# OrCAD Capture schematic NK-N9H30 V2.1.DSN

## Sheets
1 System Block: size A; title: NK-N9H30; rev: 2.1; company: nuvoTon Technology Corp.; note: System Block
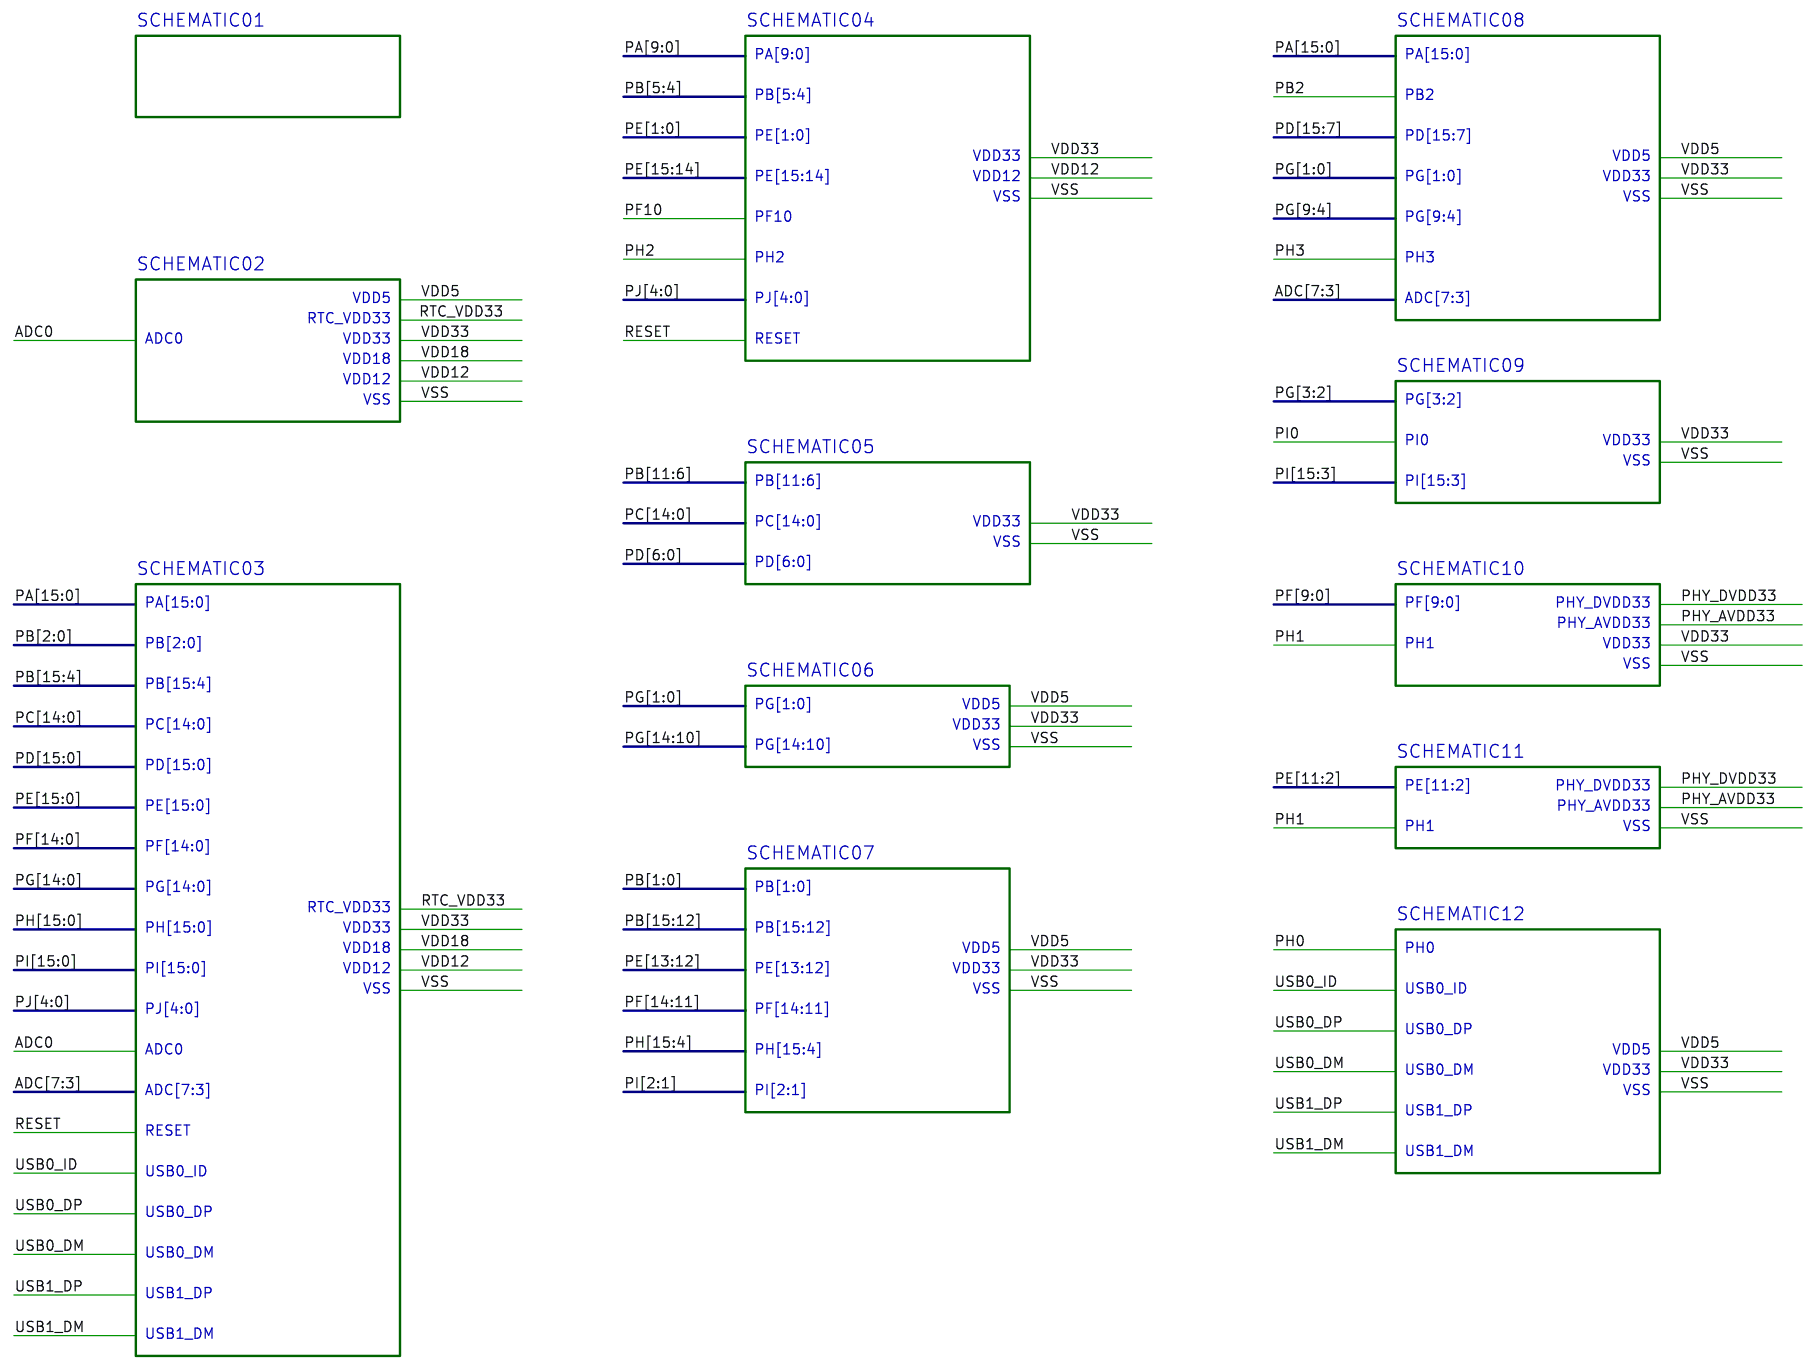
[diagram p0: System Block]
2 RMII_1_PE: size A; note: RMII_1_PE; block SCHEMATIC11
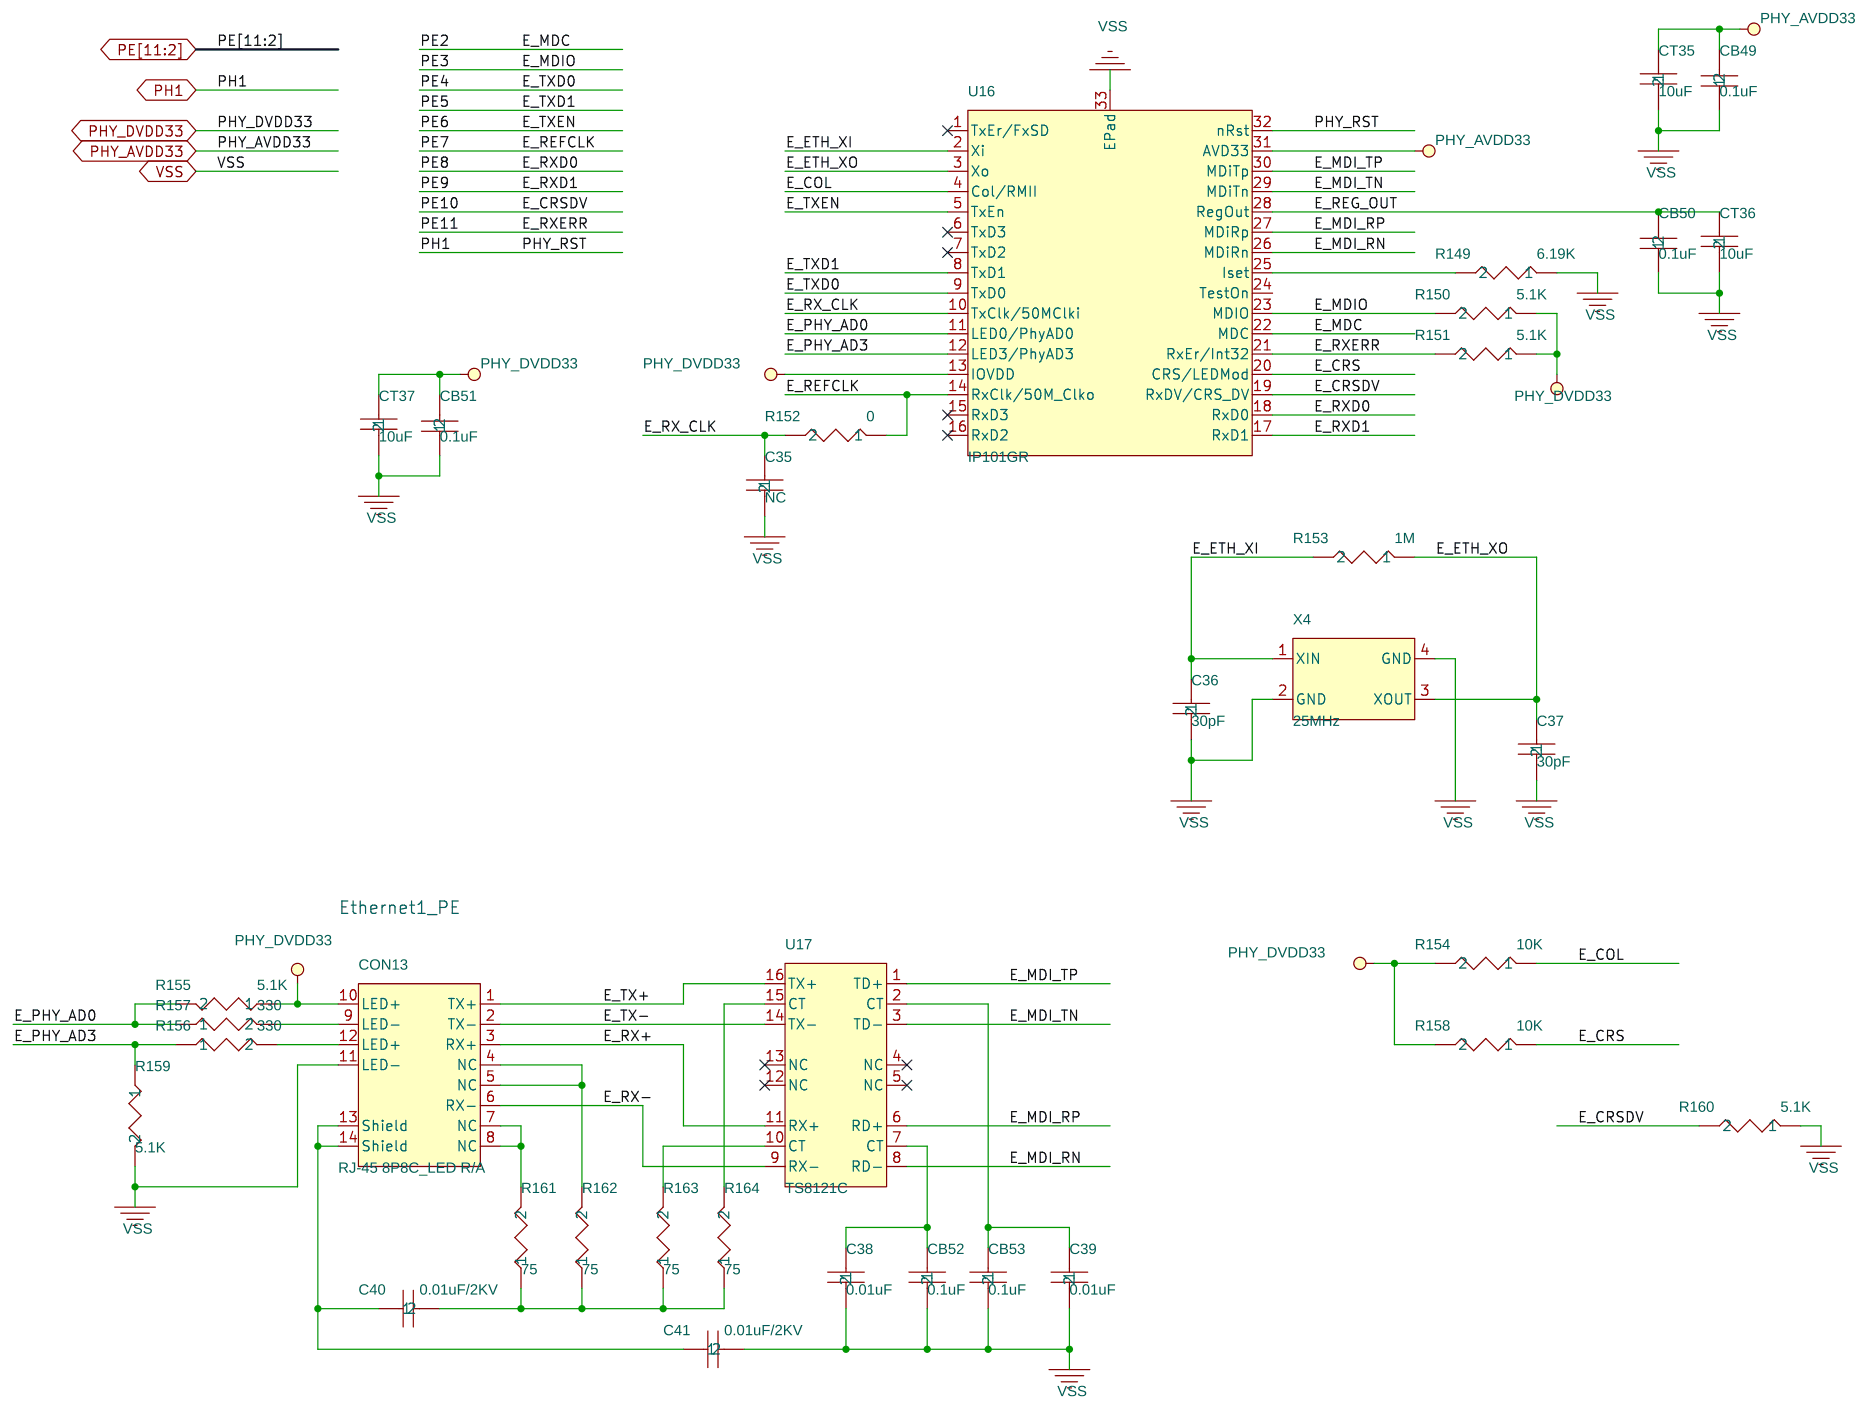
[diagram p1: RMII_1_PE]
3 RS-232_2: size A; note: RS-232_2; block SCHEMATIC07
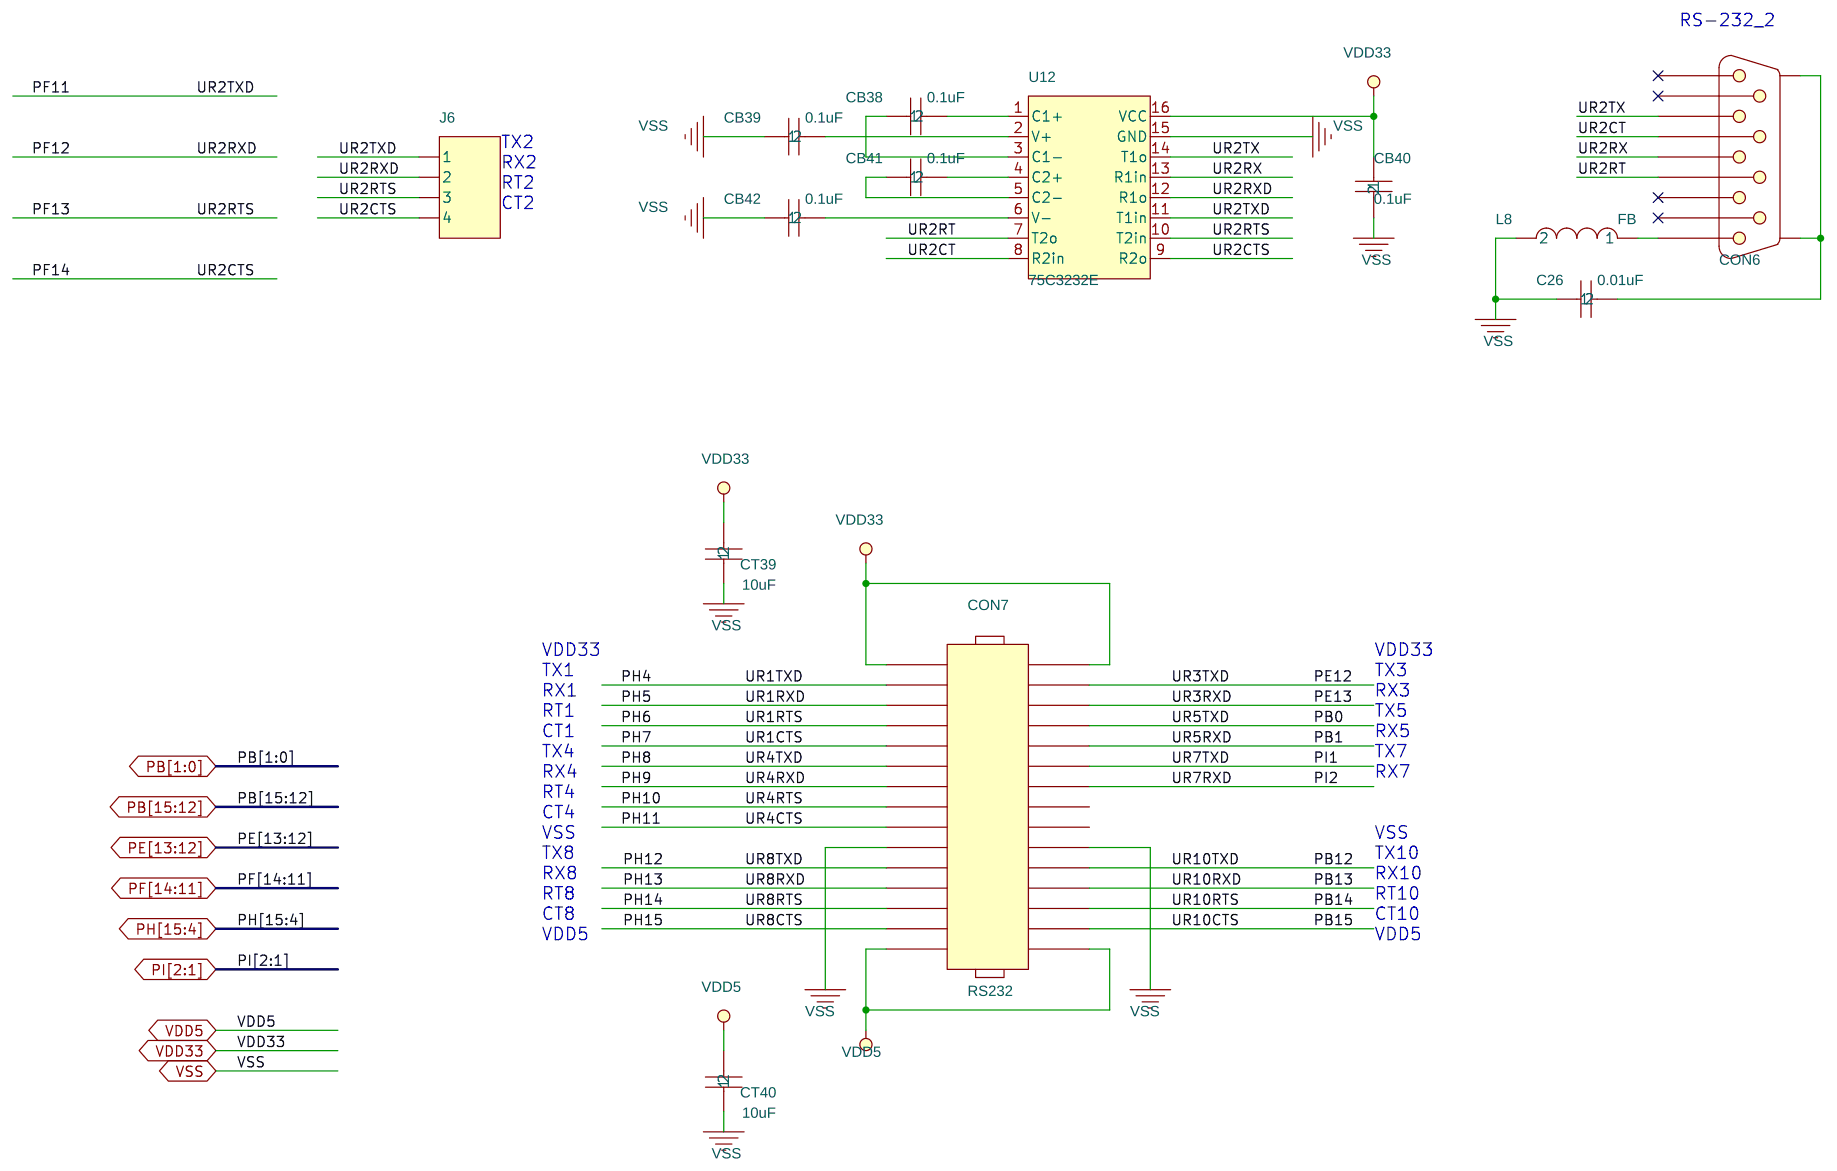
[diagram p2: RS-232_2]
4 CMOS Sensor, I2C_1, CAN_0: size A; note: CMOS Sensor, I2C_1, CAN_0; block SCHEMATIC09
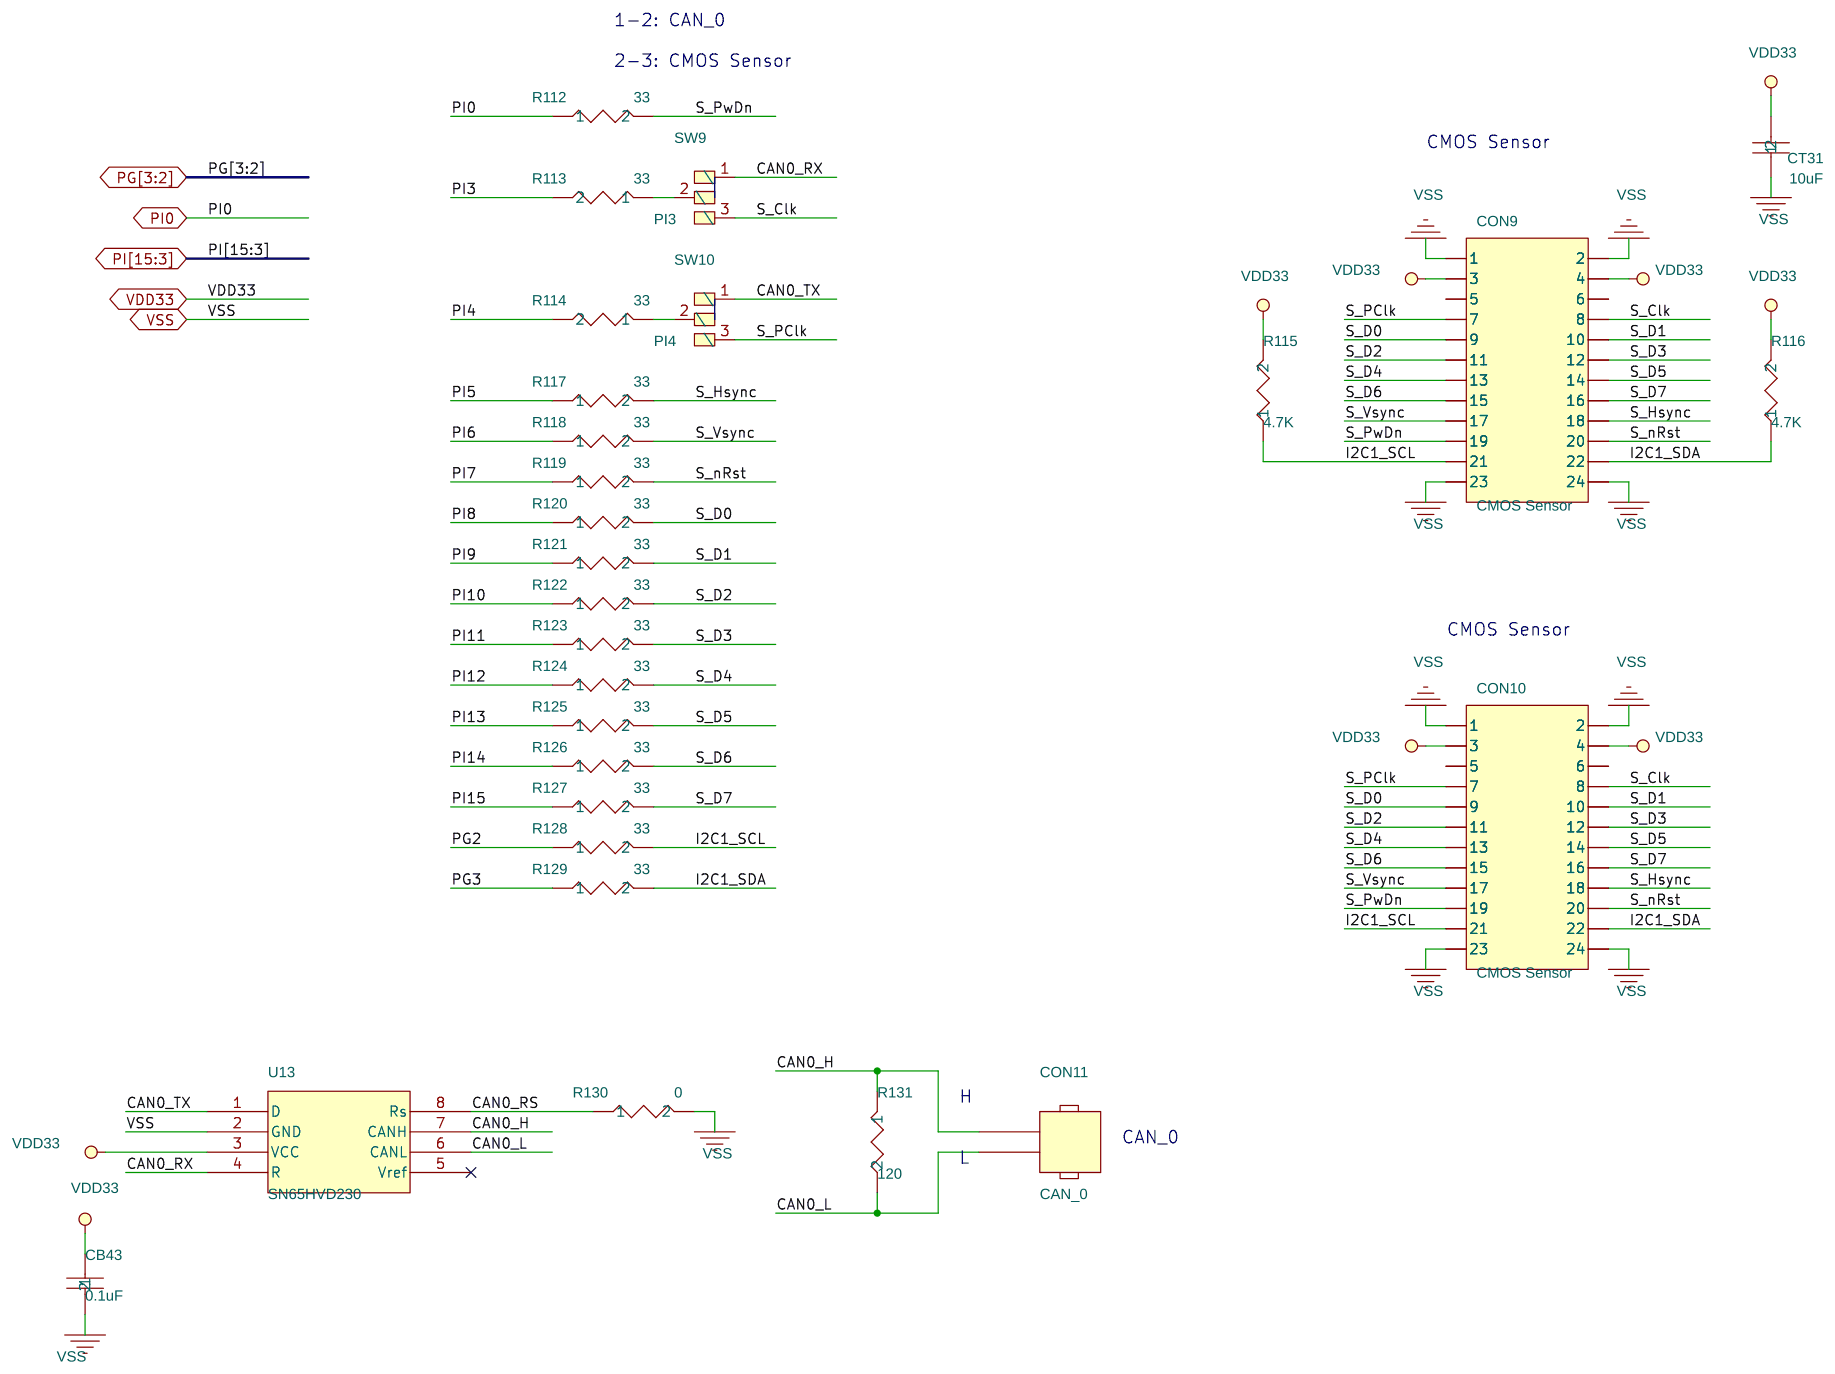
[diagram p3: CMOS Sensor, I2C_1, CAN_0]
5 I2S, I2C_0, RS-485_6: size A; note: I2S, I2C_0, RS-485_6; block SCHEMATIC06
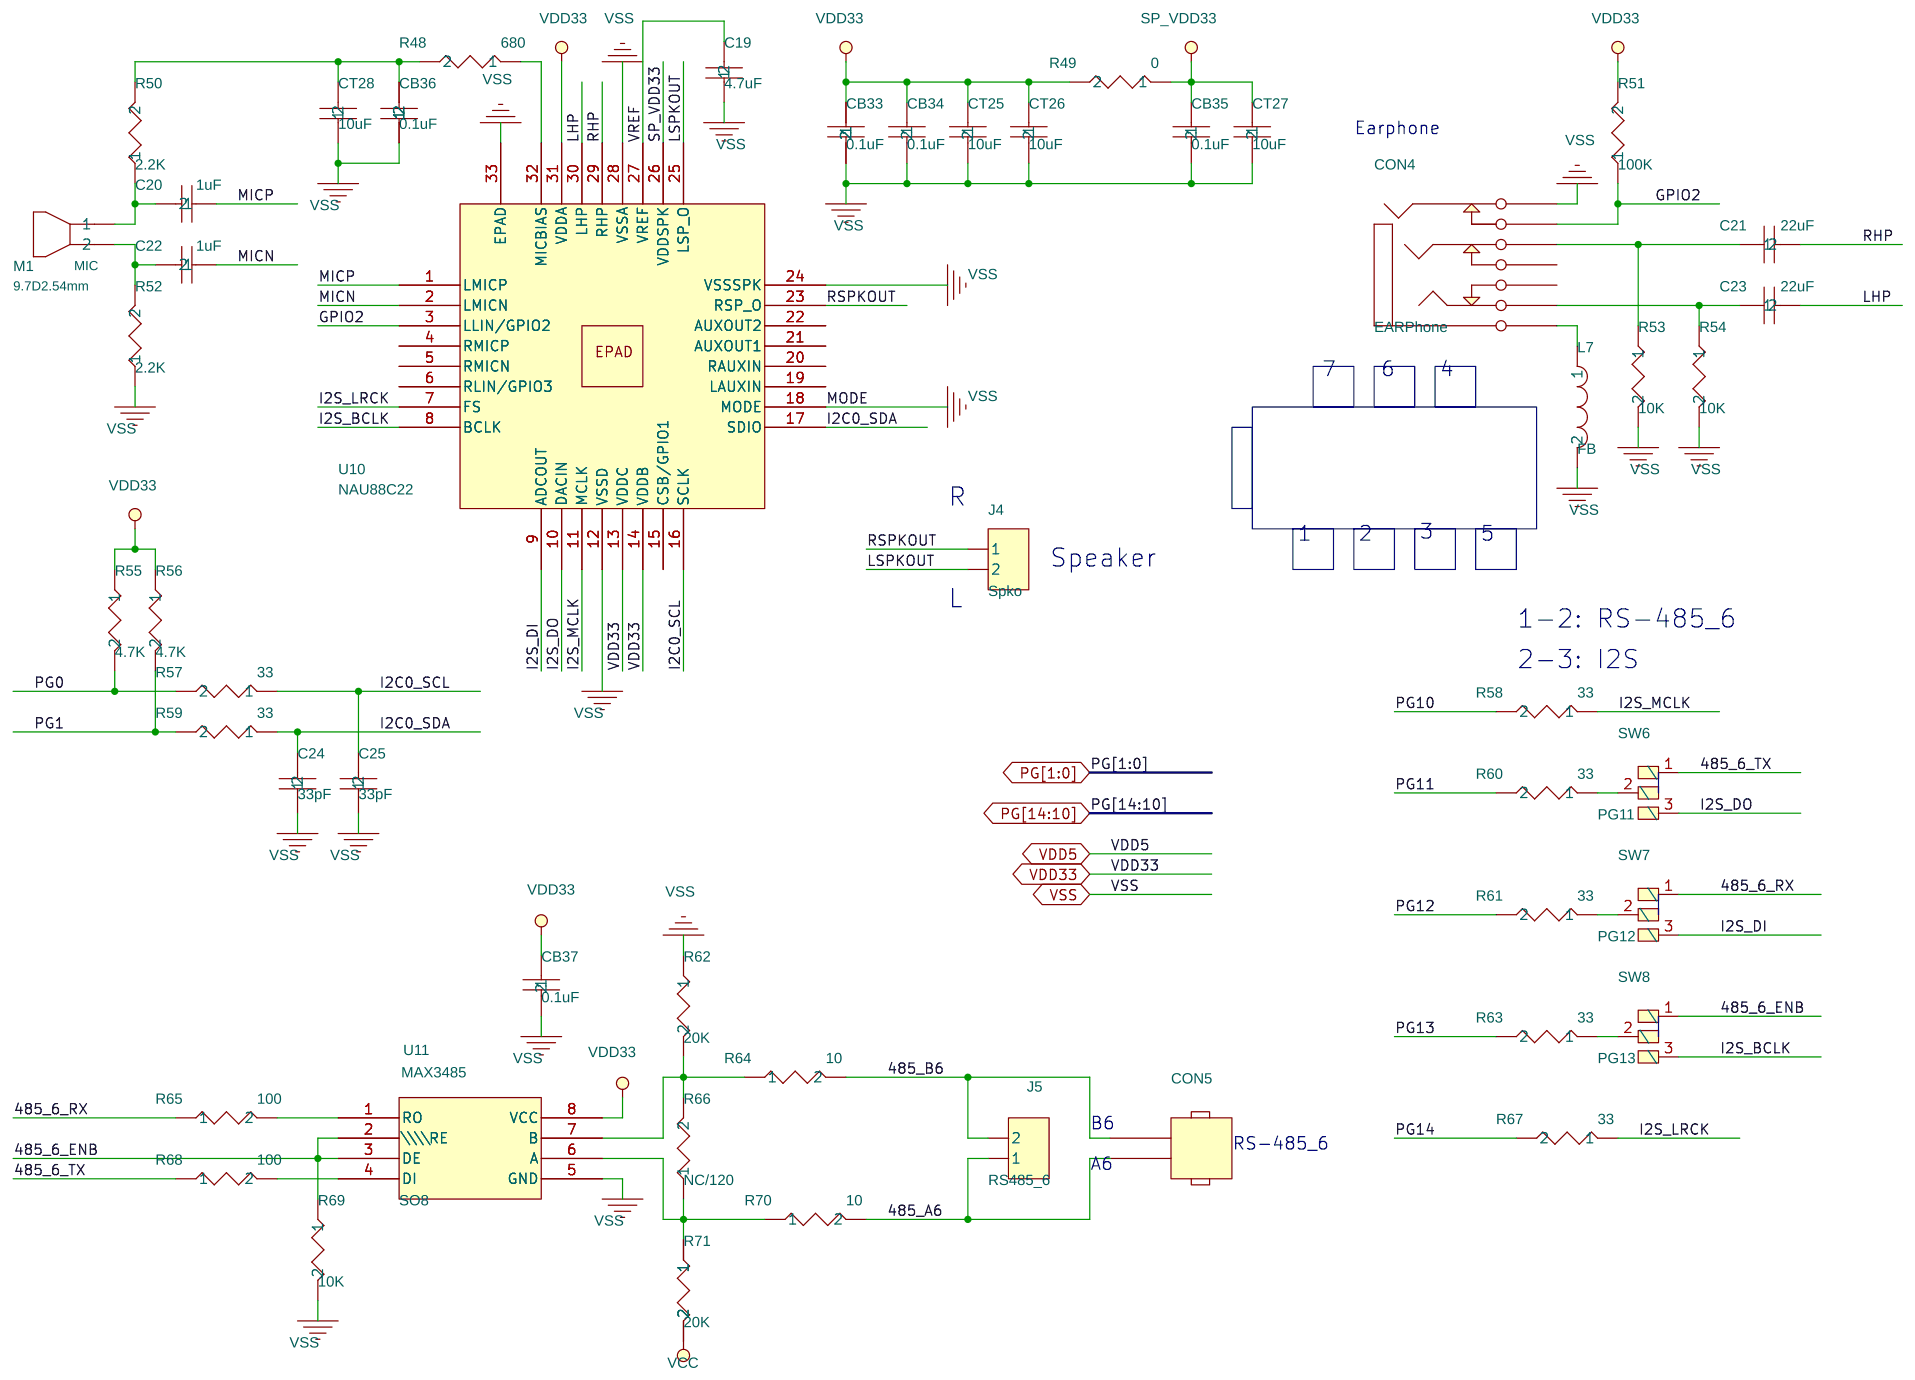
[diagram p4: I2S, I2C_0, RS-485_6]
6 LCD: size A; note: LCD; block SCHEMATIC08
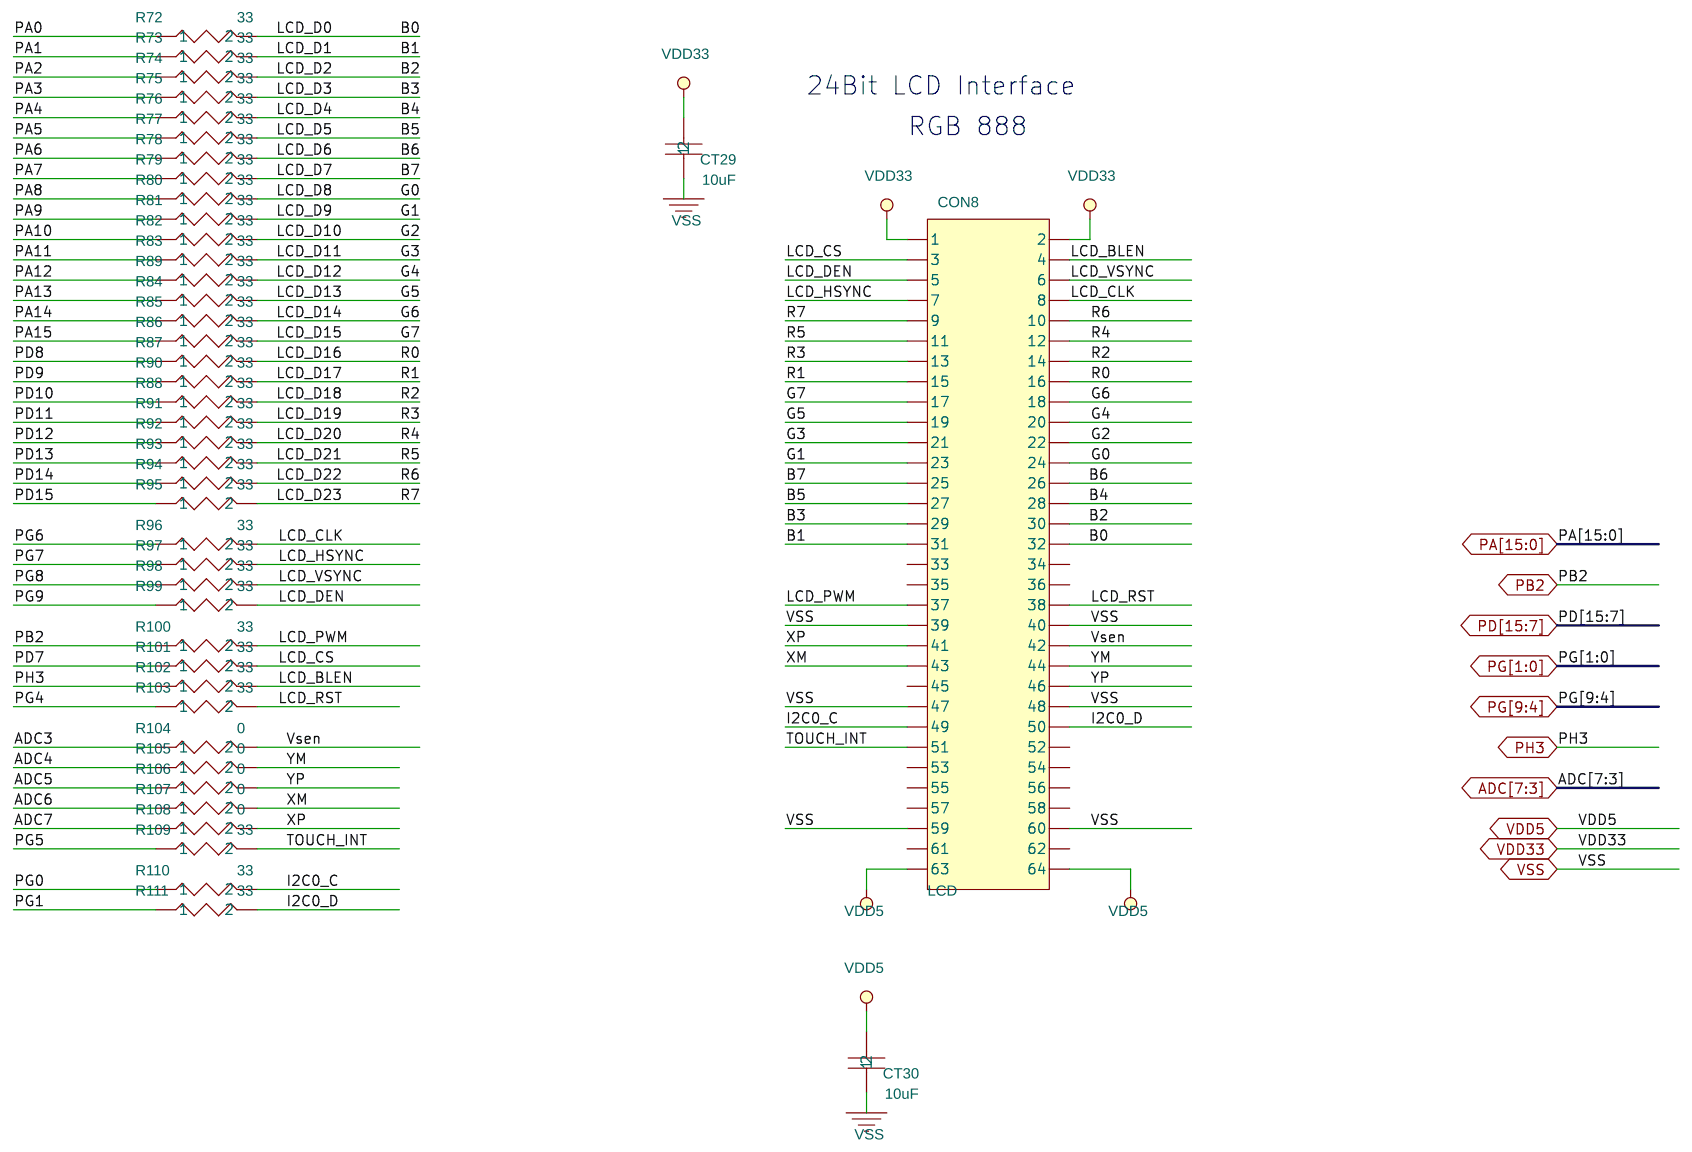
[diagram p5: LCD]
7 USB: size A; note: USB; block SCHEMATIC12
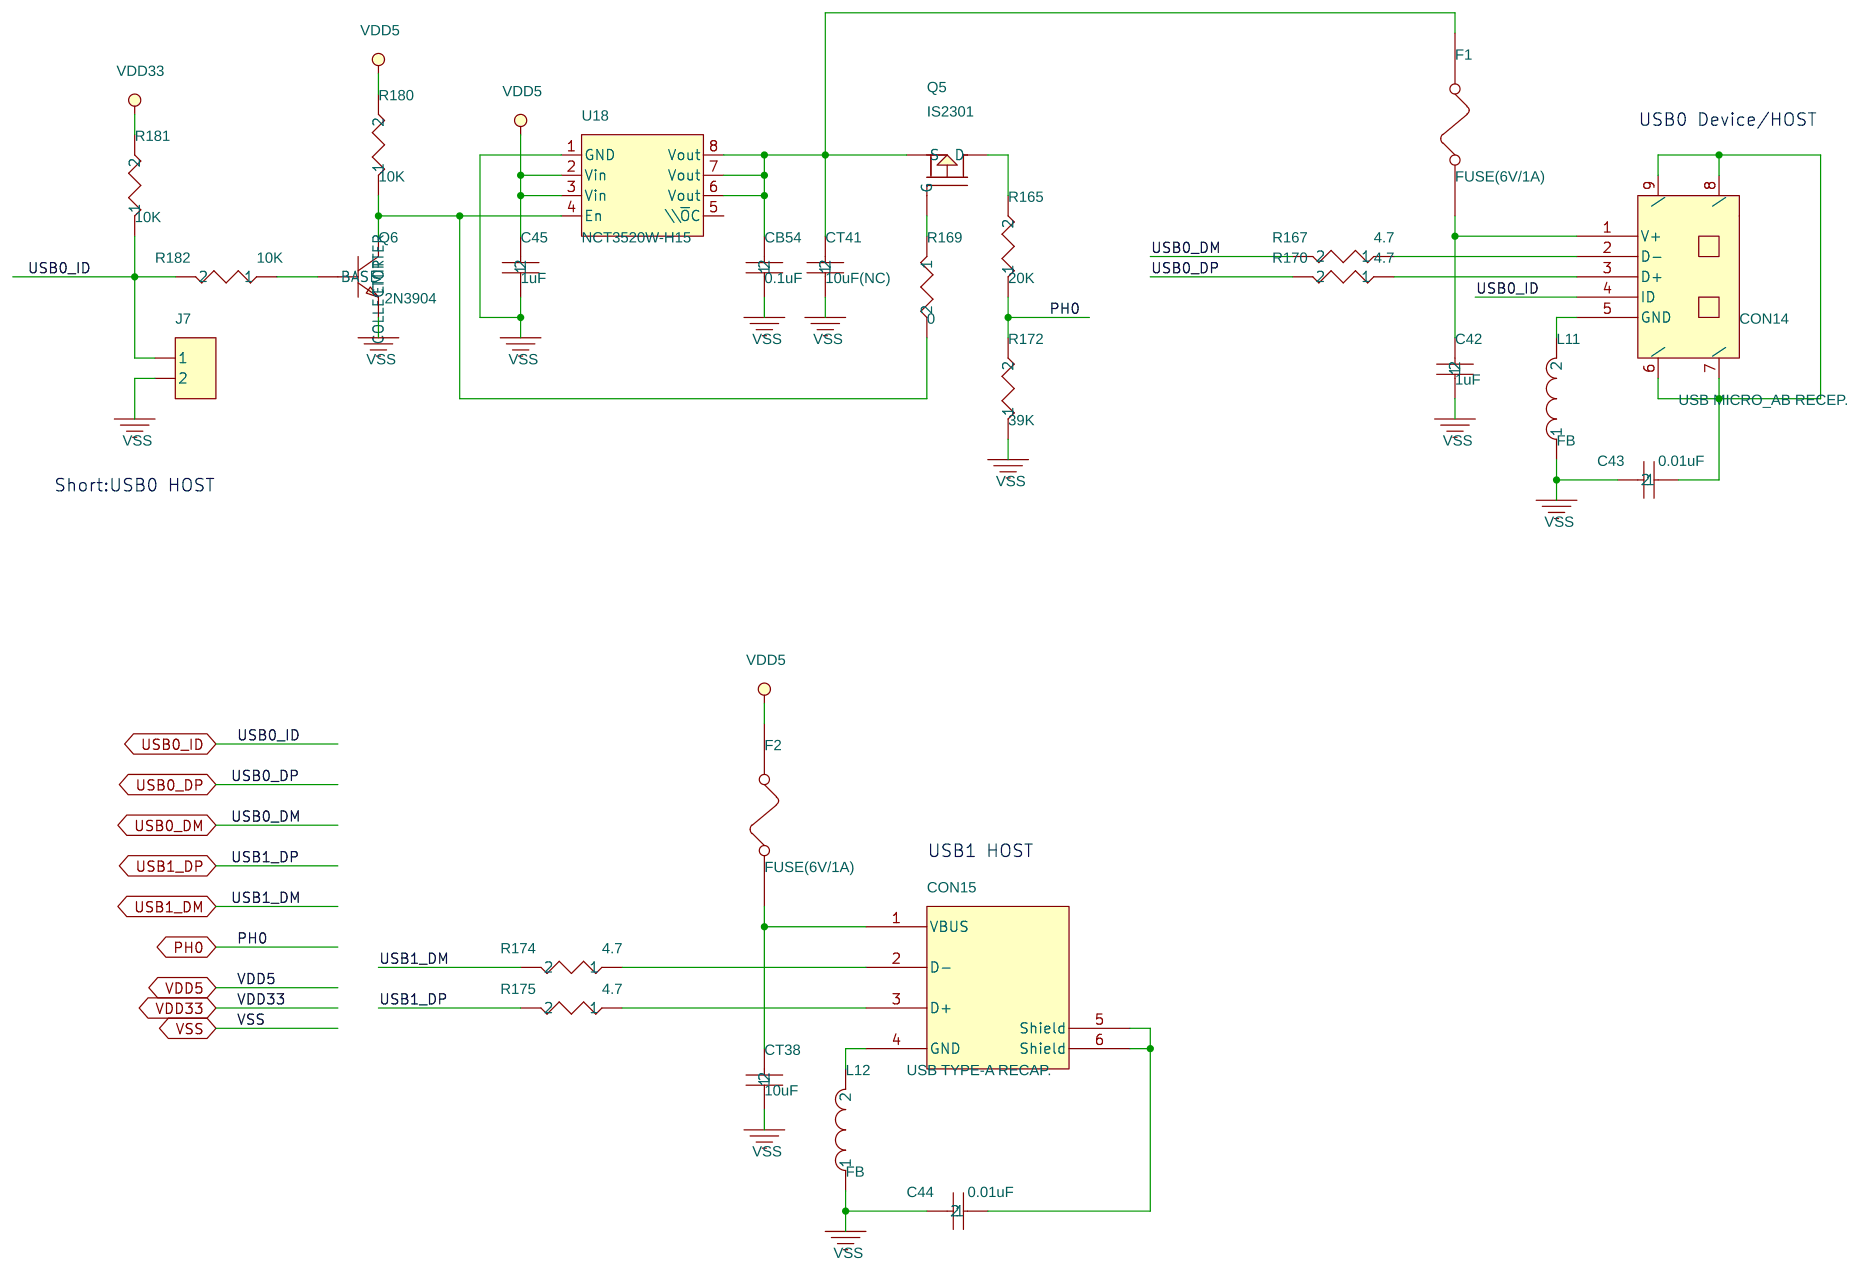
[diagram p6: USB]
8 RMII_0_PF: size A; note: RMII_0_PF; block SCHEMATIC10
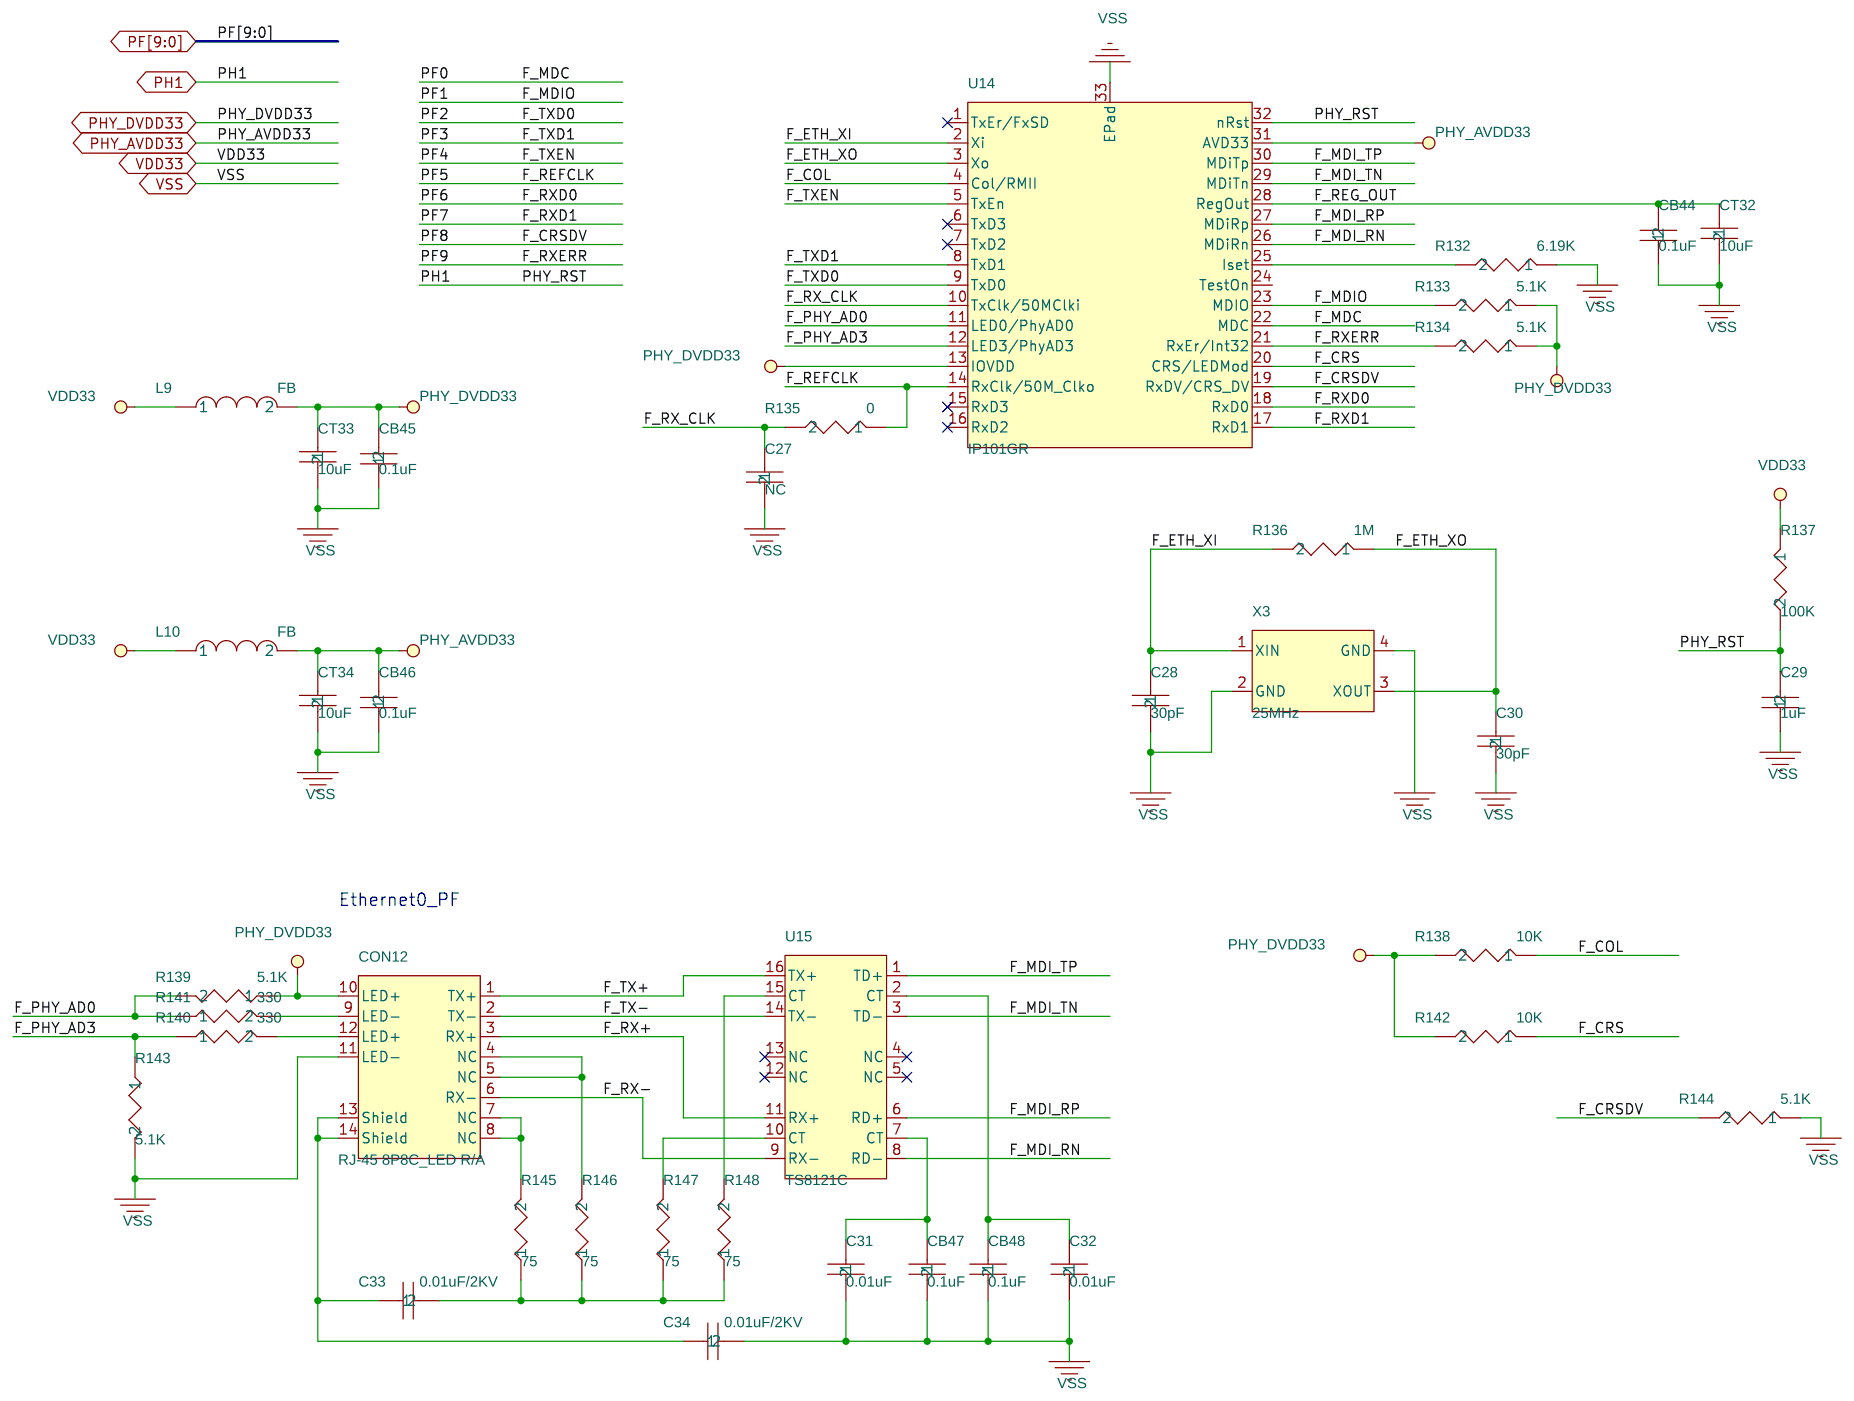
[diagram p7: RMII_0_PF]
9 Setting, ICE, RS-232_0, Key: size A; note: Setting, ICE, RS-232_0, Key; block SCHEMATIC04
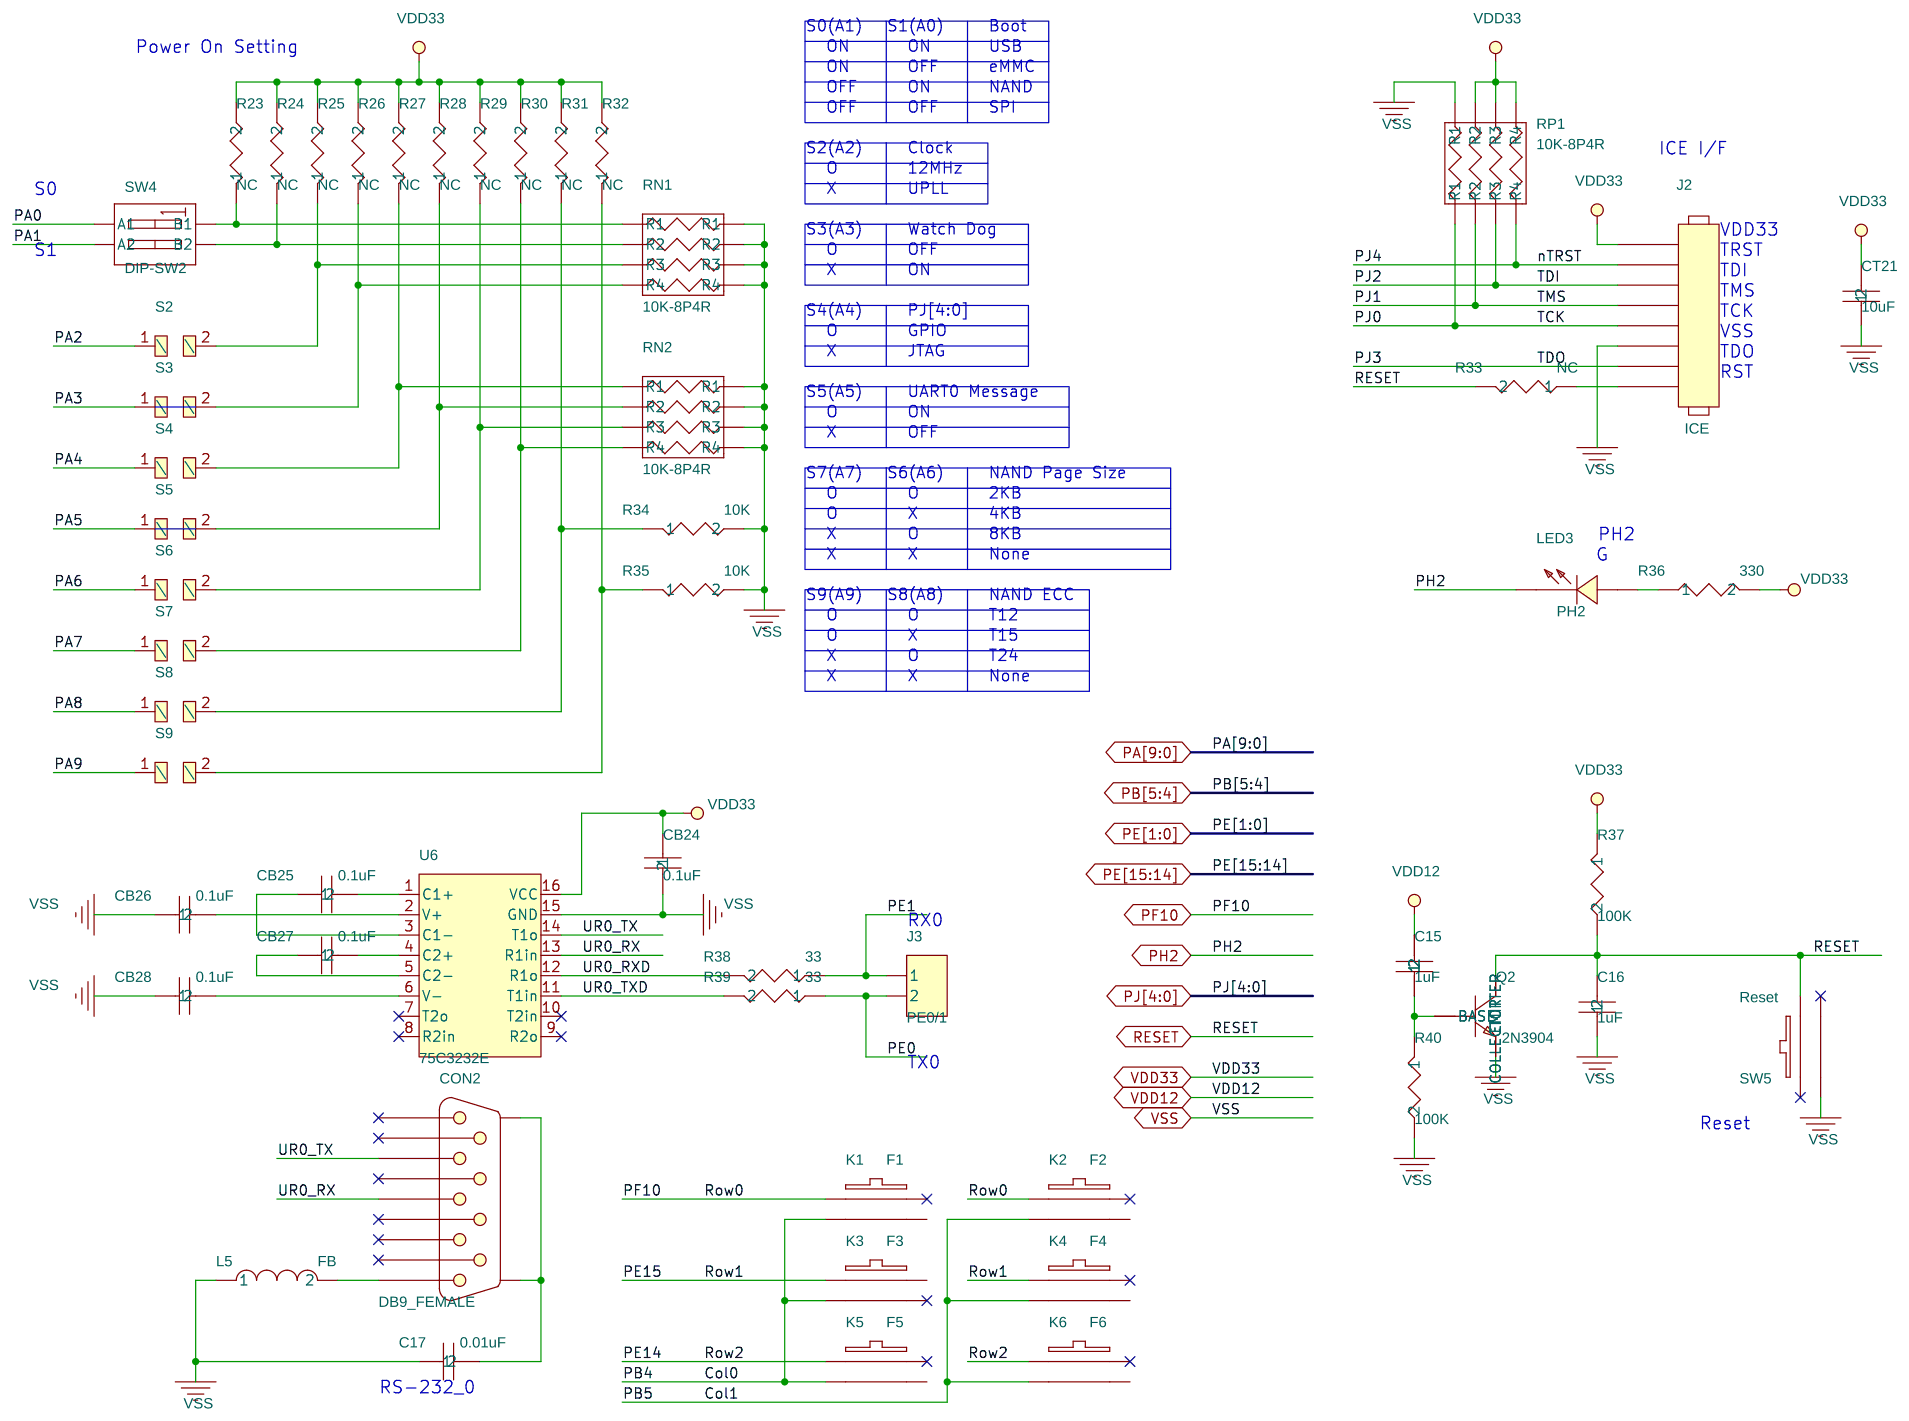
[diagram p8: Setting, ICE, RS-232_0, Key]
10 Power: size A; note: Power; block SCHEMATIC02
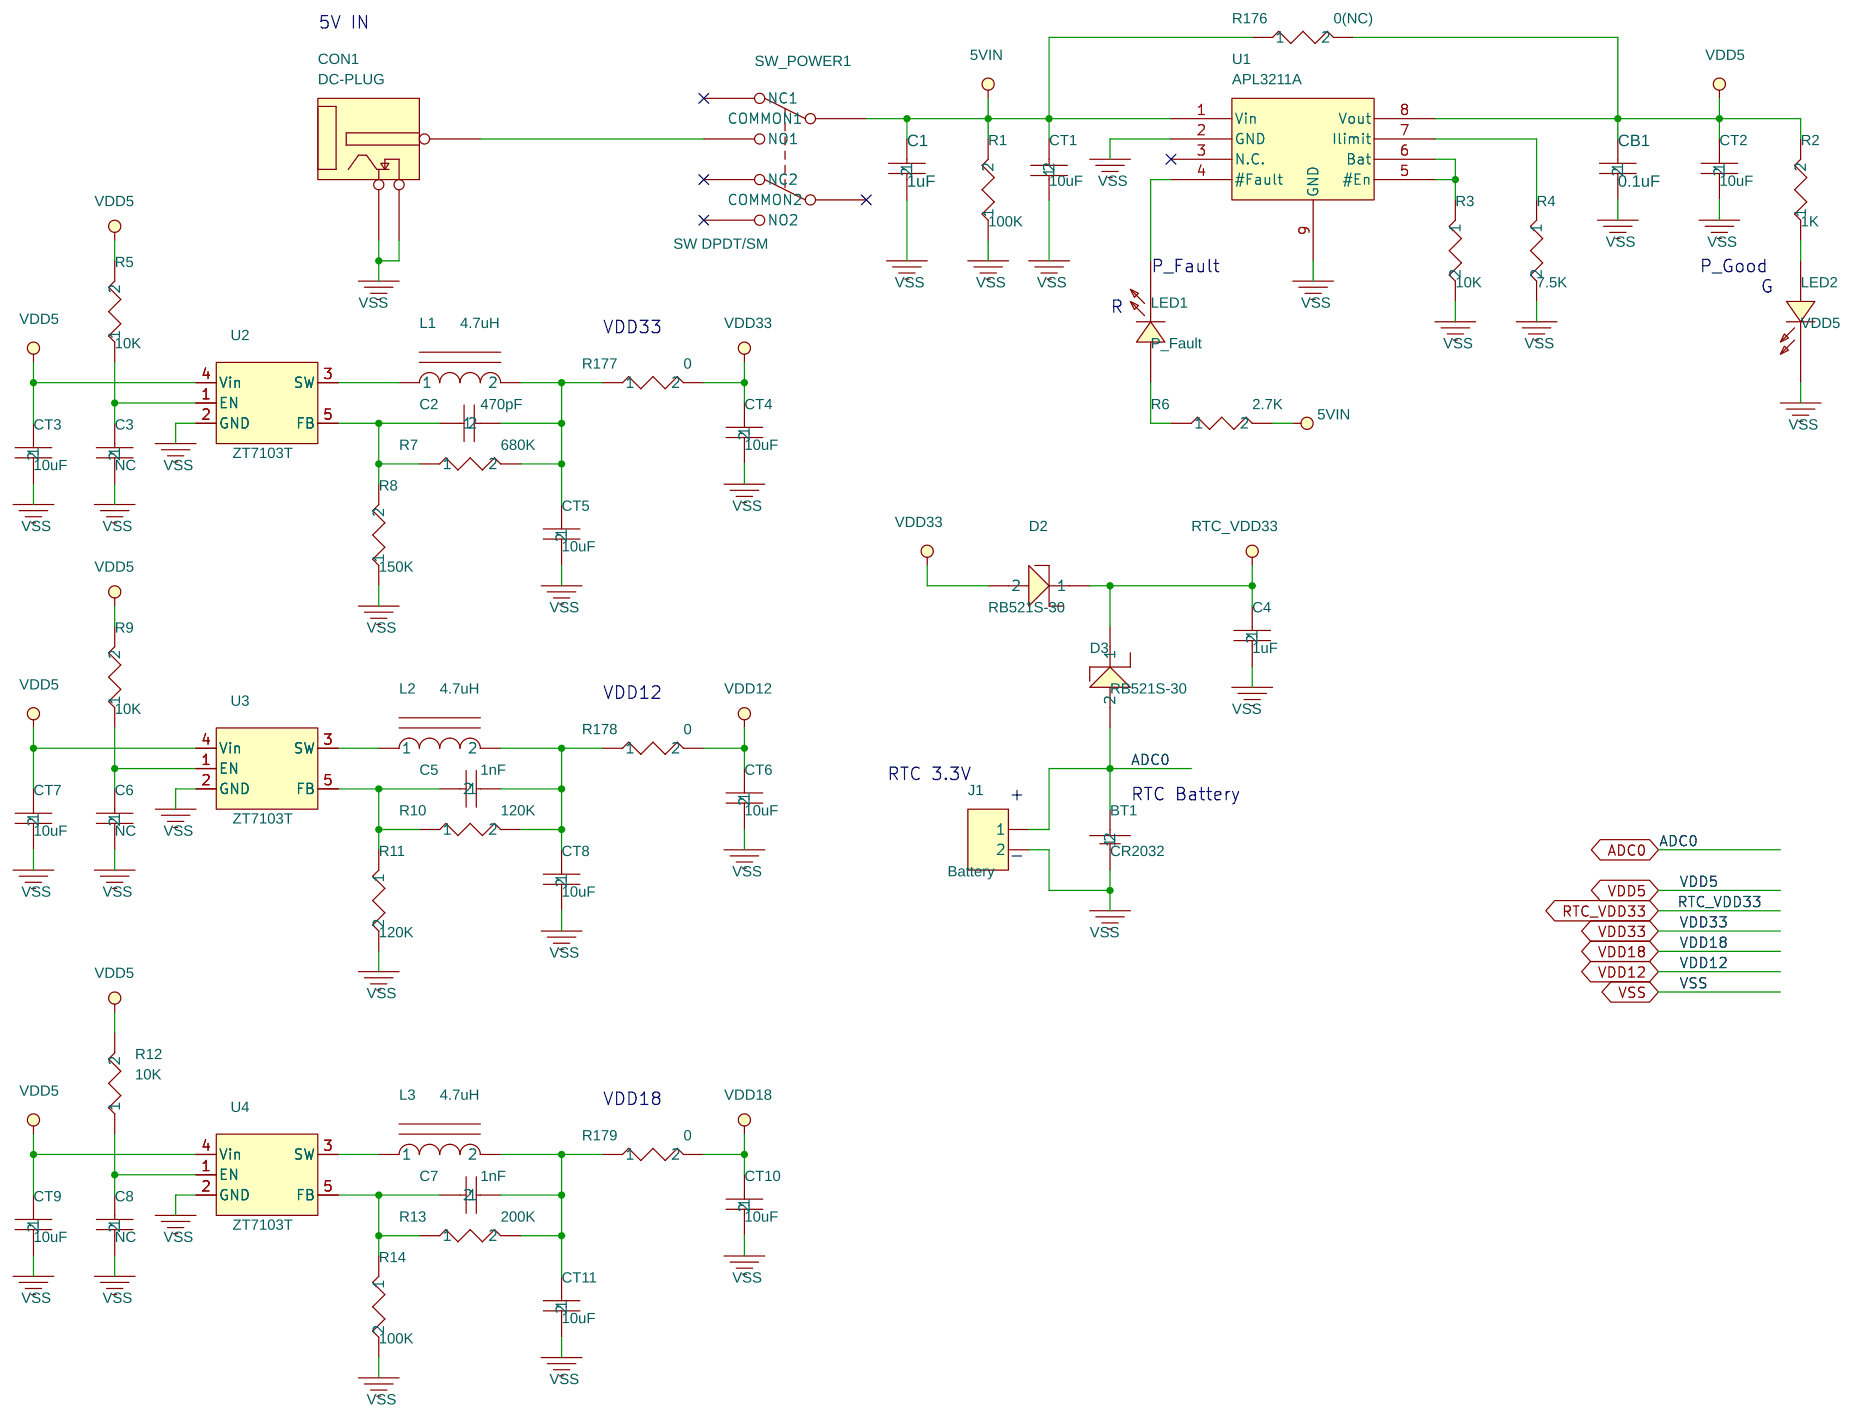
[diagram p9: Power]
11 GPIO List: note: GPIO List
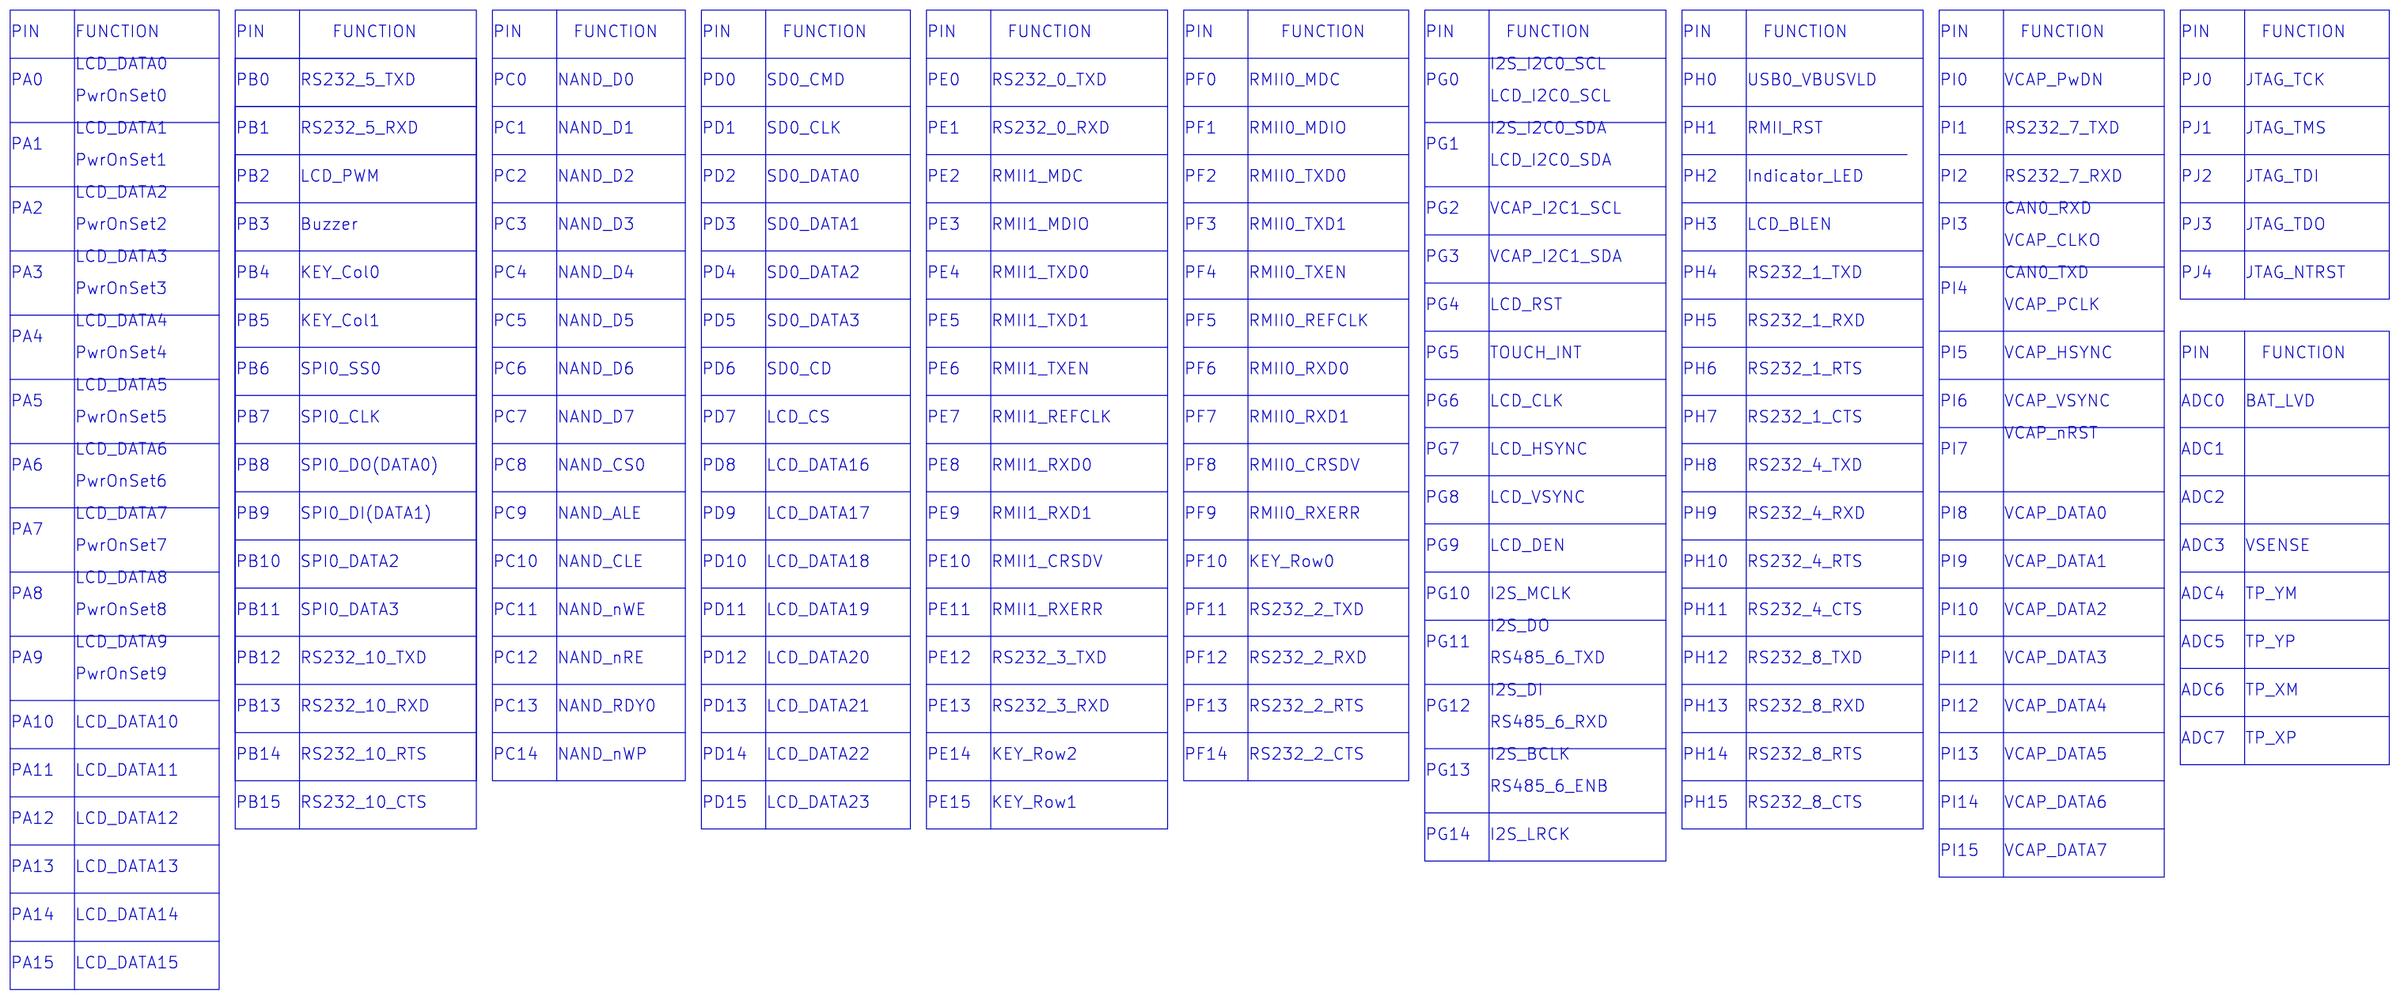
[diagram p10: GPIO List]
12 Memory: size A; note: Memory; block SCHEMATIC05
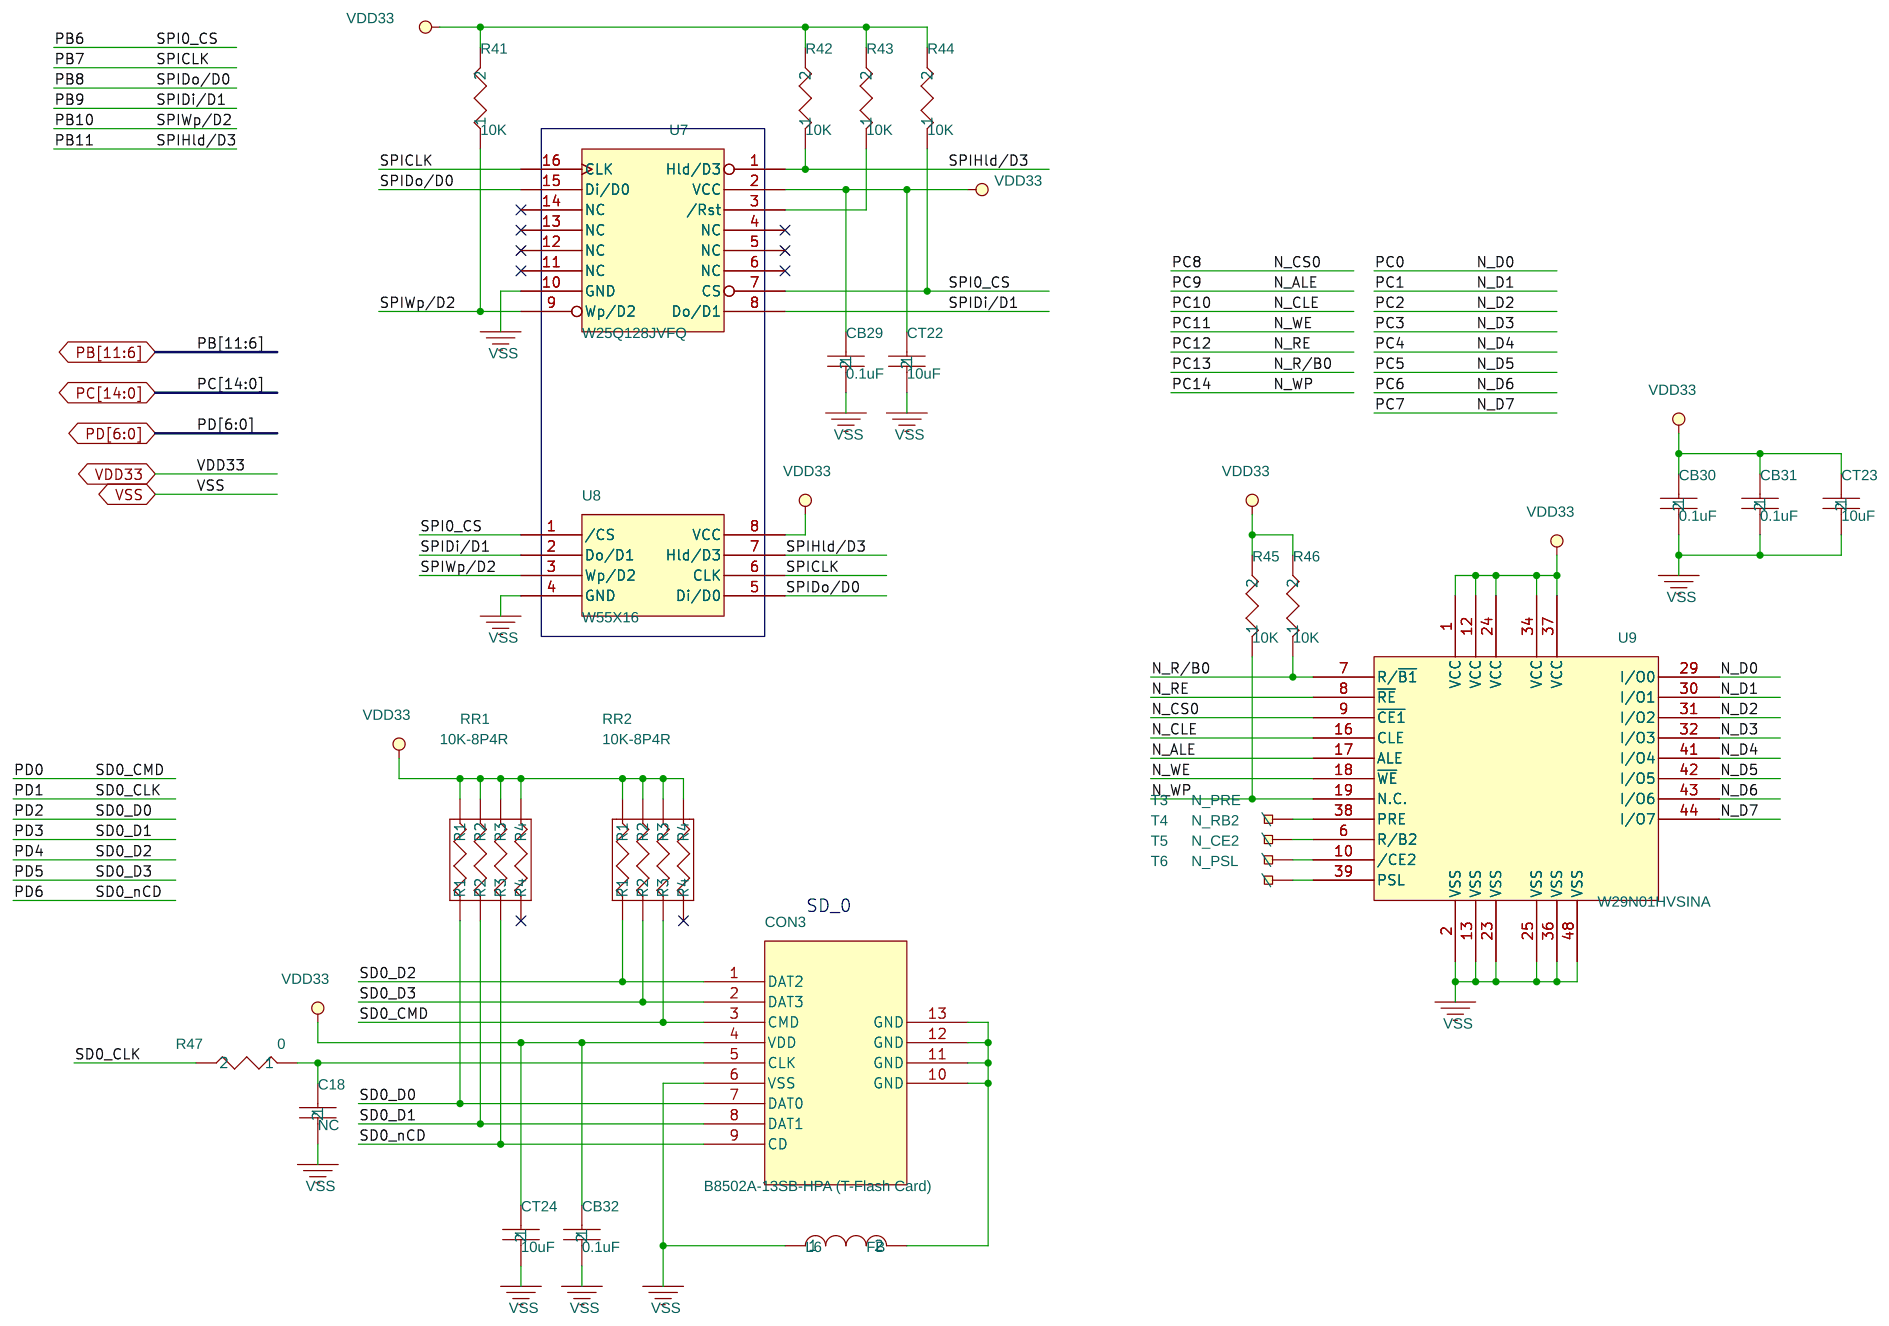
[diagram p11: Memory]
13 N9H30F61IEC: size B; note: N9H30F61IEC; block SCHEMATIC03
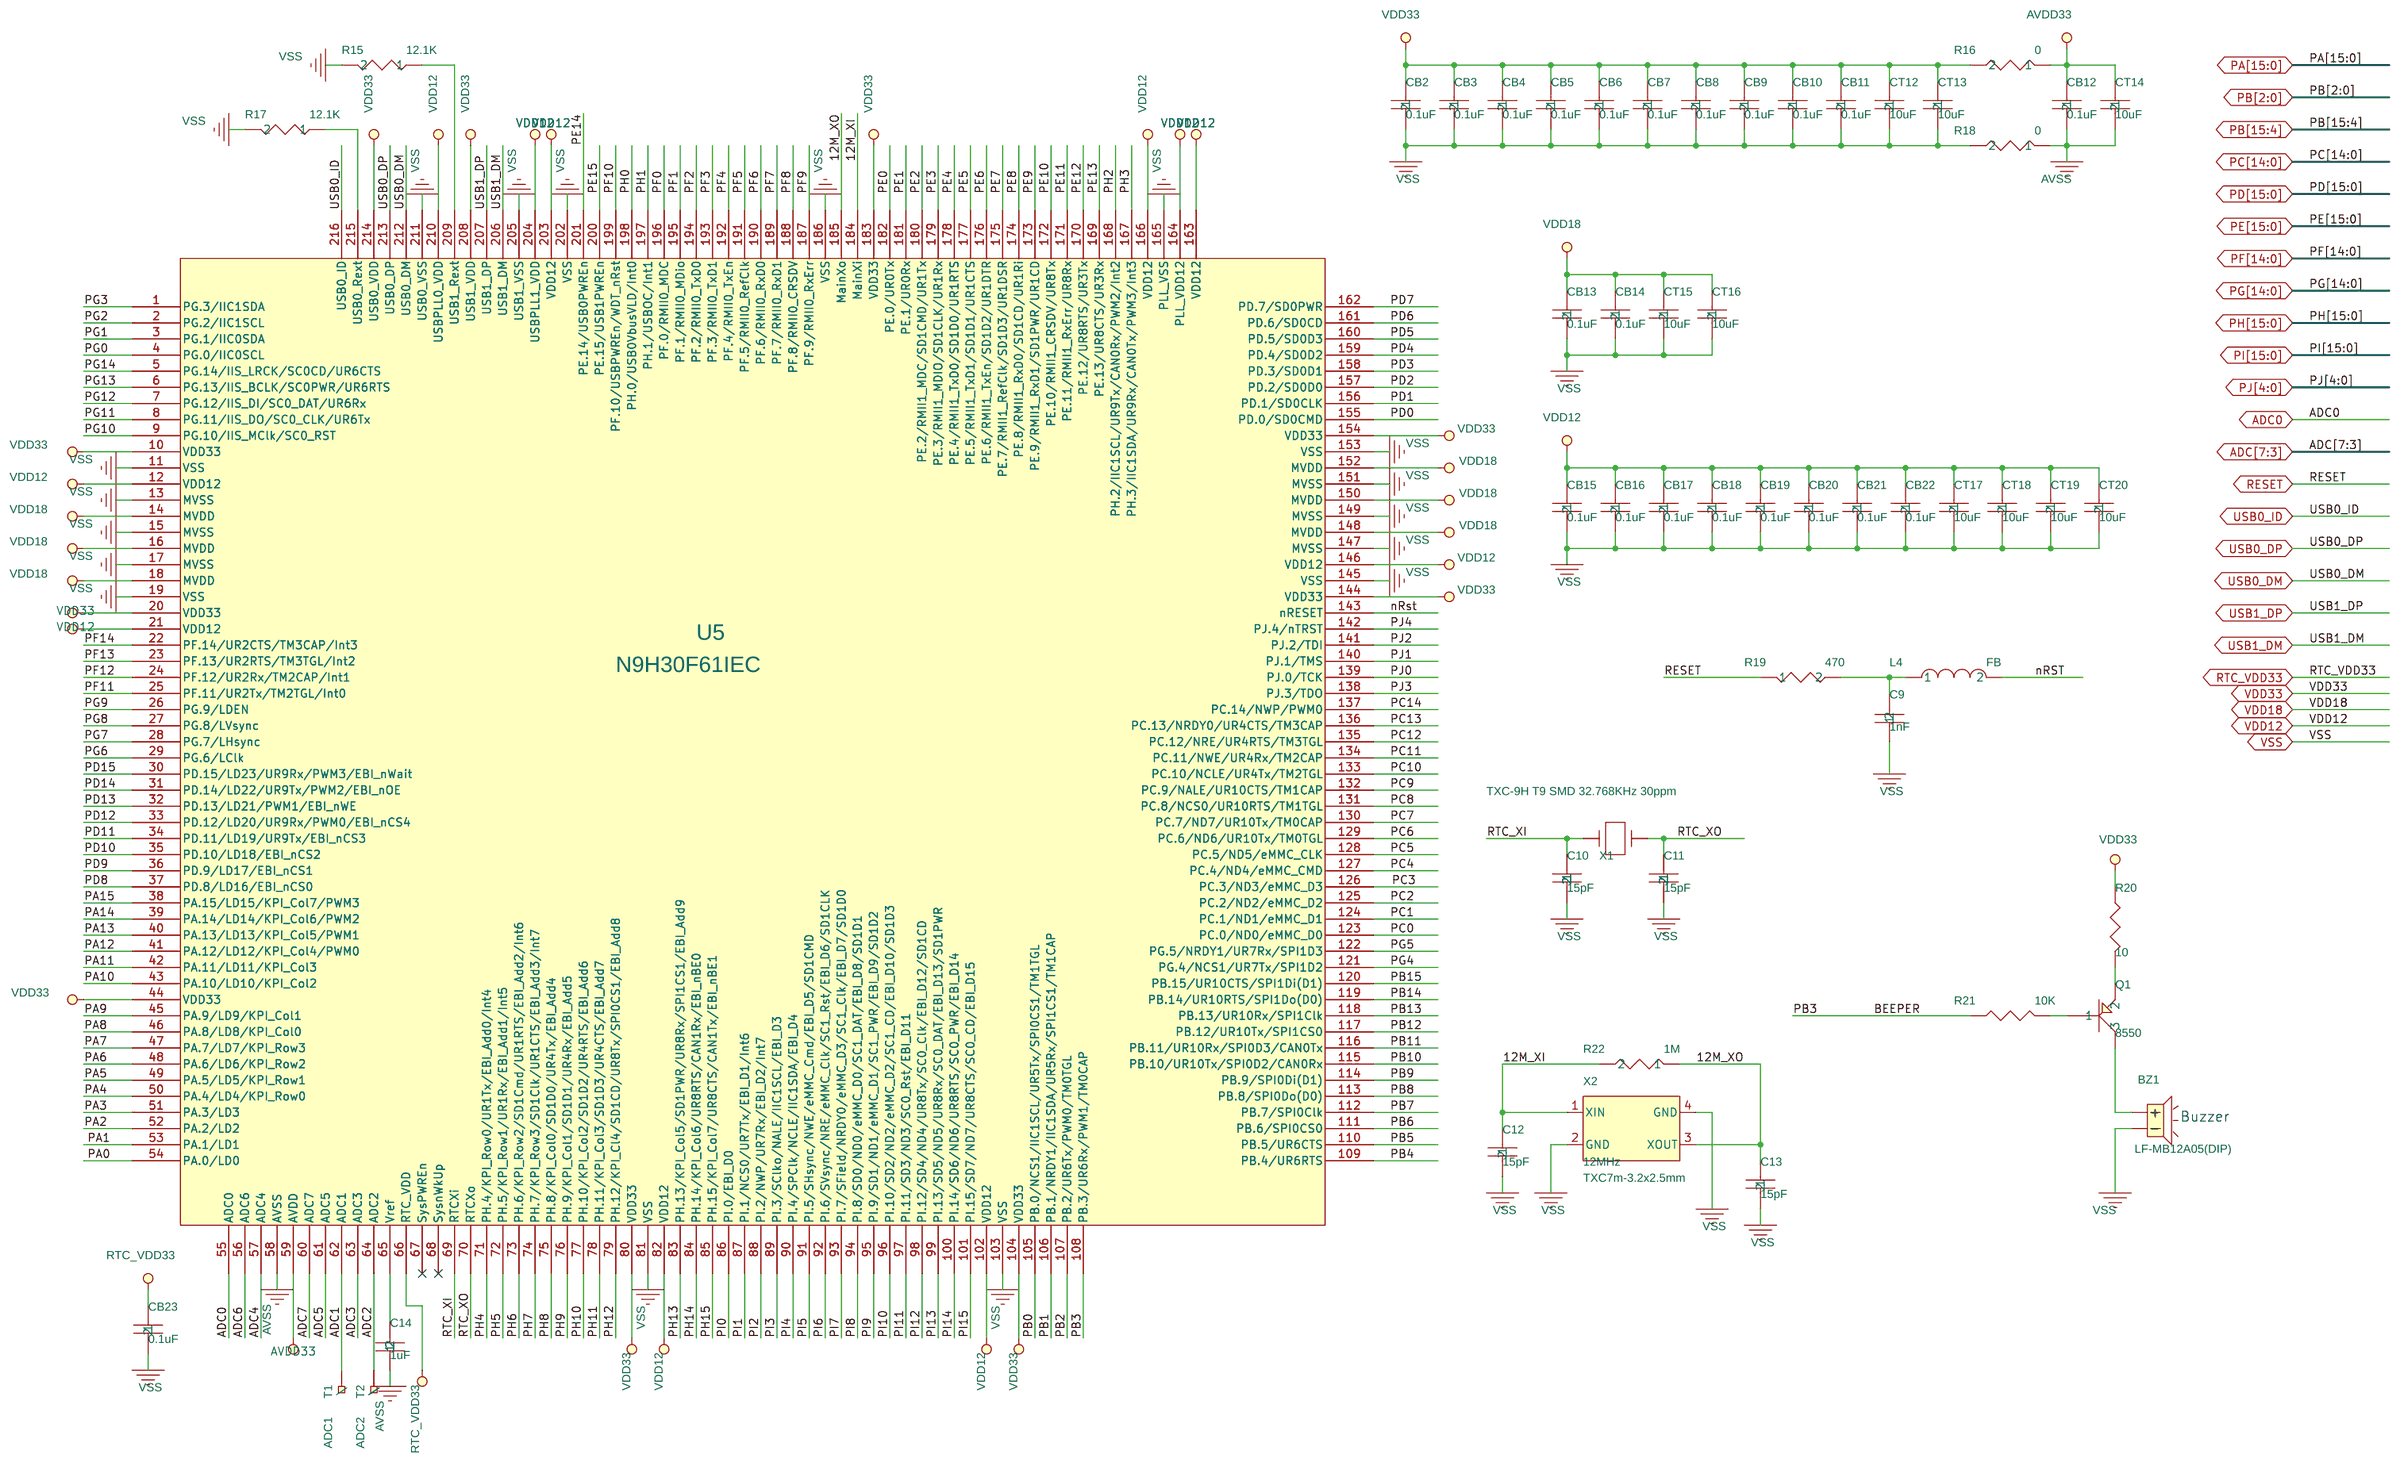
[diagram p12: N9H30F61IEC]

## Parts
sheet CMOS Sensor, I2C_1, CAN_0
CB43  0.1uF  [C0603]
CON9  CMOS Sensor  [Header_2x12_2.54mm]
CON10  CMOS Sensor  [Header_2x12_2.54mm]
CON11  CAN_0  [Header2/2.54mm_RS485]
CT31  10uF  [C0603]
R112  33  [R0603]
R113  33  [R0603]
R114  33  [R0603]
R115  4.7K  [R0603]
R116  4.7K  [R0603]
R117  33  [R0603]
R118  33  [R0603]
R119  33  [R0603]
R120  33  [R0603]
R121  33  [R0603]
R122  33  [R0603]
R123  33  [R0603]
R124  33  [R0603]
R125  33  [R0603]
R126  33  [R0603]
R127  33  [R0603]
R128  33  [R0603]
R129  33  [R0603]
R130  0  [R0603]
R131  120  [R0603]
SW9  PI3  [3P-1.2mm]
SW10  PI4  [3P-1.2mm]
U13  SN65HVD230  [SO-8-1.27X5.4M]
sheet I2S, I2C_0, RS-485_6
C19  4.7uF  [C0603]
C20  1uF  [C0603]
C21  22uF  [C0603]
C22  1uF  [C0603]
C23  22uF  [C0603]
C24  33pF  [C0603]
C25  33pF  [C0603]
CB33  0.1uF  [C0603]
CB34  0.1uF  [C0603]
CB35  0.1uF  [C0603]
CB36  0.1uF  [C0603]
CB37  0.1uF  [C0603]
CON4  EARPhone  [PHONE-PJK-631_1]
CON5  HEADER2/2.54mm_RS485  [HEADER2/2.54mm_RS485]
CT25  10uF  [C0603]
CT26  10uF  [C0603]
CT27  10uF  [C0603]
CT28  10uF  [C0603]
J4  Spko  [Header_2x1_2.54mm]
J5  RS485_6  [Header_2x1_2.54mm]
L7  FB  [L0603]
M1  MIC  [9.7D2.54mm]
R48  680  [R0603]
R49  0  [R0603]
R50  2.2K  [R0603]
R51  100K  [R0603]
R52  2.2K  [R0603]
R53  10K  [R0603]
R54  10K  [R0603]
R55  4.7K  [R0603]
R56  4.7K  [R0603]
R57  33  [R0603]
R58  33  [R0603]
R59  33  [R0603]
R60  33  [R0603]
R61  33  [R0603]
R62  20K  [R0603]
R63  33  [R0603]
R64  10  [R0603]
R65  100  [R0603]
R66  NC/120  [R0603]
R67  33  [R0603]
R68  100  [R0603]
R69  10K  [R0603]
R70  10  [R0603]
R71  20K  [R0603]
SW6  PG11  [3P-1.2mm]
SW7  PG12  [3P-1.2mm]
SW8  PG13  [3P-1.2mm]
U10  NAU88C22  [QFN32L_5x5mm\0.5mm_pitch]
U11  MAX3485  [SO8]
sheet LCD
CON8  LCD  [M_DIN_32X2/2.54A]
CT29  10uF  [C0603]
CT30  10uF  [C0603]
R72  33  [R0603]
R73  33  [R0603]
R74  33  [R0603]
R75  33  [R0603]
R76  33  [R0603]
R77  33  [R0603]
R78  33  [R0603]
R79  33  [R0603]
R80  33  [R0603]
R81  33  [R0603]
R82  33  [R0603]
R83  33  [R0603]
R84  33  [R0603]
R85  33  [R0603]
R86  33  [R0603]
R87  33  [R0603]
R88  33  [R0603]
R89  33  [R0603]
R90  33  [R0603]
R91  33  [R0603]
R92  33  [R0603]
R93  33  [R0603]
R94  33  [R0603]
R95  33  [R0603]
R96  33  [R0603]
R97  33  [R0603]
R98  33  [R0603]
R99  33  [R0603]
R100  33  [R0603]
R101  33  [R0603]
R102  33  [R0603]
R103  33  [R0603]
R104  0  [R0603]
R105  0  [R0603]
R106  0  [R0603]
R107  0  [R0603]
R108  0  [R0603]
R109  33  [R0603]
R110  33  [R0603]
R111  33  [R0603]
sheet Memory
C18  NC  [C0603]
CB29  0.1uF  [C0603]
CB30  0.1uF  [C0603]
CB31  0.1uF  [C0603]
CB32  0.1uF  [C0603]
CON3  B8502A-13SB-HPA (T-Flash Card)  [B8502A-13SB-HPA]
CT22  10uF  [C0603]
CT23  10uF  [C0603]
CT24  10uF  [C0603]
L6  FB  [0603]
R41  10K  [R0603]
R42  10K  [R0603]
R43  10K  [R0603]
R44  10K  [R0603]
R45  10K  [R0603]
R46  10K  [R0603]
R47  0  [R0603]
RR1  10K-8P4R  [8P4RA]
RR2  10K-8P4R  [8P4RA]
T3  N_PRE  [1PAD_1.25x1.25mm]
T4  N_RB2  [1PAD_1.25x1.25mm]
T5  N_CE2  [1PAD_1.25x1.25mm]
T6  N_PSL  [1PAD_1.25x1.25mm]
U7  W25Q128JVFQ  [SOIC16_300]
U8  W55X16  [SOIC8_208]
U9  W29N01HVSINA  [TSOP48-0.5mm]
sheet N9H30F61IEC
BZ1  LF-MB12A05(DIP)  [BUZZER1]
C9  1nF  [C0603]
C10  15pF  [C0603]
C11  15pF  [C0603]
C12  15pF  [C0603]
C13  15pF  [C0603]
C14  1uF  [C0603]
CB2  0.1uF  [C0603]
CB3  0.1uF  [C0603]
CB4  0.1uF  [C0603]
CB5  0.1uF  [C0603]
CB6  0.1uF  [C0603]
CB7  0.1uF  [C0603]
CB8  0.1uF  [C0603]
CB9  0.1uF  [C0603]
CB10  0.1uF  [C0603]
CB11  0.1uF  [C0603]
CB12  0.1uF  [C0603]
CB13  0.1uF  [C0603]
CB14  0.1uF  [C0603]
CB15  0.1uF  [C0603]
CB16  0.1uF  [C0603]
CB17  0.1uF  [C0603]
CB18  0.1uF  [C0603]
CB19  0.1uF  [C0603]
CB20  0.1uF  [C0603]
CB21  0.1uF  [C0603]
CB22  0.1uF  [C0603]
CB23  0.1uF  [C0603]
CT12  10uF  [C0603]
CT13  10uF  [C0603]
CT14  10uF  [C0603]
CT15  10uF  [C0603]
CT16  10uF  [C0603]
CT17  10uF  [C0603]
CT18  10uF  [C0603]
CT19  10uF  [C0603]
CT20  10uF  [C0603]
L4  FB  [0603]
Q1  8550  [SOT23]
R15  12.1K  [R0603]
R16  0  [R0603]
R17  12.1K  [R0603]
R18  0  [R0603]
R19  470  [R0603]
R20  10  [R0603]
R21  10K  [R0603]
R22  1M  [R0603]
T1  ADC1  [1PAD_1.25x1.25mm]
T2  ADC2  [1PAD_1.25x1.25mm]
U5  N9H30F61IEC  [LQFP-216]
X1  TXC-9H T9 SMD 32.768KHz 30ppm  [XTAL_2P/1.5mm]
X2  12MHz  [TXC7m-3.2x2.5mm]
sheet Power
BT1  CR2032  [BAT\CR2032-4-2]
C1  1uF  [C0603]
C2  470pF  [C0603]
C3  NC  [C0603]
C4  1uF  [C0603]
C5  1nF  [C0603]
C6  NC  [C0603]
C7  1nF  [C0603]
C8  NC  [C0603]
CB1  0.1uF  [C0603]
CON1  DC-PLUG  [POWRJACK\3P]
CT1  10uF  [C0603]
CT2  10uF  [C0603]
CT3  10uF  [C0603]
CT4  10uF  [C0603]
CT5  10uF  [C0603]
CT6  10uF  [C0603]
CT7  10uF  [C0603]
CT8  10uF  [C0603]
CT9  10uF  [C0603]
CT10  10uF  [C0603]
CT11  10uF  [C0603]
D2  RB521S-30  [SOD-523]
D3  RB521S-30  [SOD-523]
J1  Battery  [Header_2x1_2.54mm]
L1  4.7uH  [SMTDR43]
L2  4.7uH  [SMTDR43]
L3  4.7uH  [SMTDR43]
LED1  P_Fault  [LED_0805]
LED2  VDD5  [LED_0805]
R1  100K  [R0603]
R2  1K  [R0603]
R3  10K  [R0603]
R4  7.5K  [R0603]
R5  10K  [R0603]
R6  2.7K  [R0603]
R7  680K  [R0603]
R8  150K  [R0603]
R9  10K  [R0603]
R10  120K  [R0603]
R11  120K  [R0603]
R12  10K  [R0603]
R13  200K  [R0603]
R14  100K  [R0603]
R176  0(NC)  [R0603]
R177  0  [R0603]
R178  0  [R0603]
R179  0  [R0603]
SW_POWER1  SW DPDT/SM  [SW6PX]
U1  APL3211A  [TDFN2x2-8]
U2  ZT7103T  [TSOT-25]
U3  ZT7103T  [TSOT-25]
U4  ZT7103T  [TSOT-25]
sheet RMII_0_PF
C27  NC  [C0603]
C28  30pF  [C0603]
C29  1uF  [C0603]
C30  30pF  [C0603]
C31  0.01uF  [C0603]
C32  0.01uF  [C0603]
C33  0.01uF/2KV  [CK05]
C34  0.01uF/2KV  [CK05]
CB44  0.1uF  [C0603]
CB45  0.1uF  [C0603]
CB46  0.1uF  [C0603]
CB47  0.1uF  [C0603]
CB48  0.1uF  [C0603]
CON12  RJ-45 8P8C_LED R/A  [RJ45\8P\JA\LED]
CT32  10uF  [C0603]
CT33  10uF  [C0603]
CT34  10uF  [C0603]
L9  FB  [L0603]
L10  FB  [L0603]
R132  6.19K  [R0603]
R133  5.1K  [R0603]
R134  5.1K  [R0603]
R135  0  [R0603]
R136  1M  [R0603]
R137  100K  [R0603]
R138  10K  [R0603]
R139  5.1K  [R0603]
R140  330  [R0603]
R141  330  [R0603]
R142  10K  [R0603]
R143  5.1K  [R0603]
R144  5.1K  [R0603]
R145  75  [R0603]
R146  75  [R0603]
R147  75  [R0603]
R148  75  [R0603]
U14  IP101GR  [QFN32]
U15  TS8121C  [ST6200T]
X3  25MHz  [TXC7V-3.2x2.5mm]
sheet RMII_1_PE
C35  NC  [C0603]
C36  30pF  [C0603]
C37  30pF  [C0603]
C38  0.01uF  [C0603]
C39  0.01uF  [C0603]
C40  0.01uF/2KV  [CK05]
C41  0.01uF/2KV  [CK05]
CB49  0.1uF  [C0603]
CB50  0.1uF  [C0603]
CB51  0.1uF  [C0603]
CB52  0.1uF  [C0603]
CB53  0.1uF  [C0603]
CON13  RJ-45 8P8C_LED R/A  [RJ45\8P\JA\LED]
CT35  10uF  [C0603]
CT36  10uF  [C0603]
CT37  10uF  [C0603]
R149  6.19K  [R0603]
R150  5.1K  [R0603]
R151  5.1K  [R0603]
R152  0  [R0603]
R153  1M  [R0603]
R154  10K  [R0603]
R155  5.1K  [R0603]
R156  330  [R0603]
R157  330  [R0603]
R158  10K  [R0603]
R159  5.1K  [R0603]
R160  5.1K  [R0603]
R161  75  [R0603]
R162  75  [R0603]
R163  75  [R0603]
R164  75  [R0603]
U16  IP101GR  [QFN32]
U17  TS8121C  [ST6200T]
X4  25MHz  [TXC7V-3.2x2.5mm]
sheet RS-232_2
C26  0.01uF  [C0603]
CB38  0.1uF  [C0603]
CB39  0.1uF  [C0603]
CB40  0.1uF  [C0603]
CB41  0.1uF  [C0603]
CB42  0.1uF  [C0603]
CON6  DB9_FEMALE  [DB9_FMALE]
CON7  RS232  [Header_2x15_2.54mm]
CT39  10uF  [C0603]
CT40  10uF  [C0603]
J6  HEADER4/2.54mm_M
L8  FB  [0603]
U12  75C3232E  [SOP16/150]
sheet Setting, ICE, RS-232_0, Key
C15  1uF  [C0603]
C16  1uF  [C0603]
C17  0.01uF  [C0603]
CB24  0.1uF  [C0603]
CB25  0.1uF  [C0603]
CB26  0.1uF  [C0603]
CB27  0.1uF  [C0603]
CB28  0.1uF  [C0603]
CON2  DB9_FEMALE  [DB9_FMALE]
CT21  10uF  [C0603]
J2  ICE  [Header_8x1_2.54mm]
J3  PE0/1  [Header_2x1_2.54mm]
K1  F1  [STS-B5]
K2  F2  [STS-B5]
K3  F3  [STS-B5]
K4  F4  [STS-B5]
K5  F5  [STS-B5]
K6  F6  [STS-B5]
L5  FB  [0603]
LED3  PH2  [LED_0805]
Q2  2N3904  [SOT-23BEC]
R23  NC  [R0603]
R24  NC  [R0603]
R25  NC  [R0603]
R26  NC  [R0603]
R27  NC  [R0603]
R28  NC  [R0603]
R29  NC  [R0603]
R30  NC  [R0603]
R31  NC  [R0603]
R32  NC  [R0603]
R33  NC  [R0603]
R34  10K  [R0603]
R35  10K  [R0603]
R36  330  [R0603]
R37  100K  [R0603]
R38  33  [R0603]
R39  33  [R0603]
R40  100K  [R0603]
RN1  10K-8P4R  [8P4RA]
RN2  10K-8P4R  [8P4RA]
RP1  10K-8P4R  [8P4RA]
S2  SW2PH-S_3  [2P-1.2mm]
S3  SW2PH-S_3  [2P-1.2mm]
S4  SW2PH-S_3  [2P-1.2mm]
S5  SW2PH-S_3  [2P-1.2mm]
S6  SW2PH-S_3  [2P-1.2mm]
S7  SW2PH-S_3  [2P-1.2mm]
S8  SW2PH-S_3  [2P-1.2mm]
S9  SW2PH-S_3  [2P-1.2mm]
SW4  DIP-SW2  [DIPSWx2_2.54mm]
SW5  Reset  [STS-B5]
U6  75C3232E  [SOP16/150]
sheet USB
C42  1uF  [C0603]
C43  0.01uF  [C0603]
C44  0.01uF  [C0603]
C45  1uF  [C0603]
CB54  0.1uF  [C0603]
CON14  USB MICRO_AB RECEP.  [MICRO_USB_AB_LS]
CON15  USB TYPE-A RECAP.  [USB4P]
CT38  10uF  [C0603]
CT41  10uF(NC)  [C0603]
F1  FUSE(6V/1A)  [R0603]
F2  FUSE(6V/1A)  [R0603]
J7  USB  [Header_2x1_2.54mm]
L11  FB  [0603]
L12  FB  [0603]
Q5  IS2301  [SOT23-GSD]
Q6  2N3904  [SOT-23BEC]
R165  20K  [R0603]
R167  4.7  [R0603]
R169  0  [R0603]
R170  4.7  [R0603]
R172  39K  [R0603]
R174  4.7  [R0603]
R175  4.7  [R0603]
R180  10K  [R0603]
R181  10K  [R0603]
R182  10K  [R0603]
U18  NCT3520W-H15  [MSOP-8]

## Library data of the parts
C18 C20 C33 CB14 CB25 CB41 CB43 CB52 CT10 CT30 CT41 = CAP_NP_1
CON9 = CON24A
CON10 = CON24A_1
CON5 CON11 = HEADER_2
C19 C30 C40 CB18 CB24 CB29 CB39 CT5 CT29 CT31 CT38 = CAP_NP
R9 R40 R62 R106 R112 R137 = R_16
R16 R36 R41 R65 R89 R113 R132 R157 R170 R177 = R_3
R60 R84 R114 = R_19
R12 R28 R70 R105 R115 R135 R156 R165 = R_9
R3 R29 R49 R92 R116 R144 R151 = R_10
R13 R22 R33 R42 R69 R94 R117 R139 R164 R169 = R_5
R4 R39 R80 R118 R148 R158 = R_14
R6 R34 R54 R74 R119 = R_17
R15 R23 R47 R51 R79 R120 R143 R149 R174 R178 = R
R7 R18 R25 R43 R59 R108 R121 R134 R163 R175 = R_4
R27 R50 R90 R122 R146 R160 R179 R182 = R_8
R1 R31 R52 R98 R123 R140 R161 = R_12
R8 R32 R55 R100 R124 R133 R154 = R_15
R56 R86 R125 = R_18
R10 R19 R24 R46 R63 R76 R126 R141 R155 R180 = R_1
R26 R58 R82 R127 R142 R159 R176 R181 = R_7
R2 R30 R53 R102 R128 R147 R150 = R_11
R14 R35 R48 R77 R129 R138 R153 = R_13
R130 = R_2: Package: R0402
R11 R37 R45 R67 R110 R131 R145 R162 R167 = R_6
SW6-SW10 = SW-3PAD2
U13 = SN65HVD230: Package: SO-8
C21 CB49 CT8 CT19 CT34 = CAP_NP_11
C17 C22 C29 C38 CB40 CB54 CT6 CT13 CT22 = CAP_NP_5
C23 C44 CB17 CB26 CB32 CB45 CB51 CT4 CT40 = CAP_NP_3
C24 CB23 CB28 CB44 CT2 CT37 = CAP_NP_8
C25 C28 C39 CT3 CT15 = CAP_NP_10
C7 CB2 CB33 CB48 CB50 = CAP_NP_12
C6 C10 CB34 CT32 CT36 = CAP_NP_14
C3 C41 C42 CB19 CB30 CB35 CB47 CT21 CT39 = CAP_NP_4
C8 CB36 CB46 CT14 = CAP_NP_15
C1 C32 C35 CB12 CB37 = CAP_NP_13
CON4 = PHONEJACK_STEREO_SW_PJK-634_0: Package: PHONE-PJK-634M; Vendor: ÂEµX
C12 C31 C36 C45 CB27 CB42 CT1 CT23 CT25 = CAP_NP_2
C15 C34 C43 CB38 CT11 CT16 CT24 CT26 CT35 = CAP_NP_6
C2 C9 C16 C26 C27 CB31 CB53 CT27 = CAP_NP_7
C11 C37 CB1 CT28 CT33 = CAP_NP_9
J4 = CON2_1
J1 J3 J5 J7 = CON2
L4-L9 L12 = INDUCTOR
M1 = MICROPHONE_2
R57 R88 = R_21
R61 R99 = R_23
R64 R111 = R_22
R66 = R_14: Package: 0603
R68 R95 = R_20
R5 R17 R38 R44 R71 R97 R136 R152 R172 = R_2
U10 = NAU8501_0
U11 = ADM232_1: Package: DIP16\SO
CON8 = CON40A_0
R72 = R_33
R73 = R_28
R75 = R_30
R78 = R_26
R81 = R_31
R83 = R_24
R85 = R_39
R87 = R_36
R91 = R_38
R93 = R_27
R96 = R_32
R101 = R_35
R103 = R_34
R104 = R_25
R107 = R_29
R109 = R_37
CON3 = B8502A-13SB-HPA_(T-Flash_Card)
RN1 RN2 RP1 RR1 RR2 = R-PACK8_0
T1-T6 = 1PAD
U7 = W25Q128BV_4
U8 = W55X10_1_v2
U9 = NAND_4-8G_4
BZ1 = BUZZER: HUA-JIE/PAC-WT-1205-7; Class: DISCRETE; Colay_Alternate: N/A; Colay_Group: N/A; Component_Name: BUZZER/5V 2400HZ 87DB; Critical_Part: N; Data_Sheet: K:\DataSheet\09-INDUCTOR\09G050000400.pdf; Manufacture: HUAJIE; Modify_Data: 2005/5/9; Optional: N/A; Package_Type: DIP; Part Number: 09G050000400; Part Type: 09INDUCTOR\BUZZER; Subsystem_ID: N/A; metal_fabrication: 00000011
C13 = CAP_NP_34
C14 = CAP_NP_27
CB3 CT7 = CAP_NP_17
CB4 = CAP_NP_21
CB5 = CAP_NP_24
CB6 = CAP_NP_33
CB7 = CAP_NP_29
CB8 = CAP_NP_22
CB9 = CAP_NP_26
CB10 = CAP_NP_32
CB11 = CAP_NP_35
CB13 = CAP_NP_31
CB15 CT9 = CAP_NP_19
CB16 = CAP_NP_30
C4 CB20 = CAP_NP_16
CB21 = CAP_NP_23
CB22 = CAP_NP_28
CT12 = CAP_NP_36
CT17 = CAP_NP_20
CT18 = CAP_NP_25
C5 CT20 = CAP_NP_18
Q1 = PNP_1
R20 R21 = R_0: Package: 0603
U5 = NUC970_9
X1 = MA306_SM_2: Vendor: TXC
X2 = Crystal_SMD_2
BT1 = BATTERY_ELEM
CON1 = Power_Jack
D2 D3 = ZENAR_0: Package: D
L1 = INDUCTOR_IRON
L2 = INDUCTOR_IRON_2
L3 = INDUCTOR_IRON_1
LED1-LED3 = LED
SW_POWER1 = SW_DPDT_SM
U1 = APL3203A_1
U2-U4 = ZT7103S_0
CON12 CON13 = RJ45_SHLD_0
L10 L11 = INDUCTOR_1
U14 U16 = IP101GA_3
U15 U17 = PE-68515_1
X3 X4 = Crystal_SMD_2: Vendor: Aurum
CON2 CON6 = CONNECTOR_DB9_0
CON7 = HEADER_15X2
J6 = HEADER_4_1
U6 U12 = ADM232_0
J2 = HEADER_8
K1 = SW-S_1
K2 = SW-S
K3 = SW-S_3
K4 = SW-S_6
K5 = SW-S_5
K6 = SW-S_4
Q2 Q6 = NPN
S2-S9 = SW2PH-S_3
SW4 = SW_DIP-2_0
SW5 = SW-S_2
CON14 = USB_Type_B_0
CON15 = USB_type_A_connector
F1 F2 = FUSE
Q5 = MOSFET_P_4
U18 = NCT3520W-H10_1

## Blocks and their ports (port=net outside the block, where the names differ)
SCHEMATIC01 = schematic SCHEMATIC01, on sheet System Block: no ports
SCHEMATIC08 = schematic SCHEMATIC08, on sheet System Block: PA[15:0], PG[9:4], ADC[7:3], VDD33, VSS, VDD5, PD[15:7], PB2, PH3, PG[1:0]
SCHEMATIC11 = schematic SCHEMATIC11, on sheet System Block: PH1, PHY_DVDD33, PE[11:2], PHY_AVDD33, VSS
SCHEMATIC03 = schematic SCHEMATIC03, on sheet System Block: RTC_VDD33, VSS, VDD33, VDD18, VDD12, PA[15:0], PB[2:0], PC[14:0], PD[15:0], PE[15:0], PF[14:0], PG[14:0], PH[15:0], PI[15:0], PJ[4:0], ADC[7:3], ADC0, RESET, PB[15:4], USB0_DP, USB0_ID, USB0_DM, USB1_DP, USB1_DM
SCHEMATIC06 = schematic SCHEMATIC06, on sheet System Block: VDD33, VSS, PG[1:0], PG[14:10], VDD5
SCHEMATIC05 = schematic SCHEMATIC05, on sheet System Block: PB[11:6], PD[6:0], VDD33, VSS, PC[14:0]
SCHEMATIC07 = schematic SCHEMATIC07, on sheet System Block: VSS, VDD33, PE[13:12], PF[14:11], PI[2:1], PB[1:0], PB[15:12], PH[15:4], VDD5
SCHEMATIC10 = schematic SCHEMATIC10, on sheet System Block: PH1, PHY_DVDD33, PF[9:0], PHY_AVDD33, VDD33, VSS
SCHEMATIC04 = schematic SCHEMATIC04, on sheet System Block: PA[9:0], PF10, VDD12, PB[5:4], PE[15:14], RESET, VSS, VDD33, PJ[4:0], PE[1:0], PH2
SCHEMATIC02 = schematic SCHEMATIC02, on sheet System Block: ADC0, VDD12, RTC_VDD33, VSS, VDD18, VDD33, VDD5
SCHEMATIC09 = schematic SCHEMATIC09, on sheet System Block: PI0, VDD33, PI[15:3], PG[3:2], VSS
SCHEMATIC12 = schematic SCHEMATIC12, on sheet System Block: PH0, USB0_DP, USB0_DM, USB1_DP, USB1_DM, VDD33, VSS, USB0_ID, VDD5

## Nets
5VIN: C1.1 CT1.2 R1.2 R6.2 R176.1 SW_POWER1.2(COMMON1) U1.1(Vin)
AVDD33: CB12.1 CT14.1 R16.1 U5.59(AVDD)
AVSS: C14.1 CB12.2 CT14.2 R18.1 U5.58(AVSS)
VDD5: C45.2 CB1.1 CON7.29 CON7.30 CON8.63 CON8.64 CT2.1 CT3.1 CT7.1 CT9.1 CT30.2 CT40.2 F2.2 R2.2 R5.2 R9.2 R12.2 R71.2 R176.2 R180.2 U1.8(Vout) U2.4(Vin) U3.4(Vin) U4.4(Vin) U18.2(Vin) U18.3(Vin)
VDD12: C15.2 CB15.1 CB16.1 CB17.1 CB18.1 CB19.1 CB20.1 CB21.1 CB22.1 CT6.1 CT17.1 CT18.1 CT19.1 CT20.1 R178.2 U5.12(VDD12) U5.21(VDD12) U5.82(VDD12) U5.102(VDD12) U5.146(VDD12) U5.163(VDD12) U5.164(PLL_VDD12) U5.166(VDD12) U5.203(VDD12) U5.204(USBPLL1_VDD) U5.210(USBPLL0_VDD)
VDD18: CB13.1 CB14.1 CT10.1 CT15.1 CT16.1 R179.2 U5.14(MVDD) U5.16(MVDD) U5.18(MVDD) U5.148(MVDD) U5.150(MVDD) U5.152(MVDD)
VDD33: CB2.1 CB3.1 CB4.1 CB5.1 CB6.1 CB7.1 CB8.1 CB9.1 CB10.1 CB11.1 CB24.1 CB29.1 CB30.1 CB31.1 CB32.1 CB33.1 CB34.1 CB37.1 CB40.1 CB43.1 CON3.4(VDD) CON7.1 CON7.2 CON8.1 CON8.2 CON9.3 CON9.4 CON10.3 CON10.4 CT4.1 CT12.1 CT13.1 CT21.2 CT22.1 CT23.1 CT24.1 CT25.1 CT26.1 CT29.2 CT31.2 CT39.2 D2.1(2) J2.1 L9.1 L10.1 R16.2 R20.1 R23.2 R24.2 R25.2 R26.2 R27.2 R28.2 R29.2 R30.2 R31.2 R32.2 R36.2 R37.1 R41.2 R42.2 R43.2 R44.2 R45.2 R46.2 R49.2 R51.2 R55.1 R56.1 R115.2 R116.2 R137.1 R177.2 R181.2 RP1.4(R2) RP1.6(R3) RP1.8(R4) RR1.2(R1) RR1.4(R2) RR1.6(R3) RR1.8(R4) RR2.2(R1) RR2.4(R2) RR2.6(R3) RR2.8(R4) U5.10(VDD33) U5.20(VDD33) U5.44(VDD33) U5.80(VDD33) U5.104(VDD33) U5.144(VDD33) U5.154(VDD33) U5.183(VDD33) U5.208(USB1_VDD) U5.214(USB0_VDD) U6.16(VCC) U7.2(VCC) U8.8(VCC) U9.1(VCC) U9.12(VCC) U9.24(VCC) U9.34(VCC) U9.37(VCC) U10.13(VDDC) U10.14(VDDB) U10.31(VDDA) U11.8(VCC) U12.16(VCC) U13.3(VCC)
VSS: BT1.1 BZ1.2(-) C1.2 C3.2 C4.2 C6.2 C8.2 C9.1 C10.2 C11.2 C12.2 C13.2 C16.1 C17.1 C18.2 C19.1 C24.1 C25.1 C26.1 C27.2 C28.2 C29.1 C30.2 C31.2 C32.2 C34.2 C35.2 C36.2 C37.2 C38.2 C39.2 C41.2 C42.1 C43.2 C44.2 C45.1 CB1.2 CB2.2 CB3.2 CB4.2 CB5.2 CB6.2 CB7.2 CB8.2 CB9.2 CB10.2 CB11.2 CB13.2 CB14.2 CB15.2 CB16.2 CB17.2 CB18.2 CB19.2 CB20.2 CB21.2 CB22.2 CB23.2 CB24.2 CB26.1 CB28.1 CB29.2 CB30.2 CB31.2 CB32.2 CB33.2 CB34.2 CB35.2 CB36.1 CB37.2 CB39.1 CB40.2 CB42.1 CB43.2 CB44.1 CB45.1 CB46.1 CB47.2 CB48.2 CB49.1 CB50.1 CB51.1 CB52.2 CB53.2 CB54.1 CON1.2 CON1.3 CON3.6(VSS) CON4.2 CON7.19 CON7.20 CON8.39 CON8.40 CON8.47 CON8.48 CON8.59 CON8.60 CON9.1 CON9.2 CON9.23 CON9.24 CON10.1 CON10.2 CON10.23 CON10.24 CON12.11(LED-) CON13.11(LED-) CT1.1 CT2.2 CT3.2 CT4.2 CT5.2 CT6.2 CT7.2 CT8.2 CT9.2 CT10.2 CT11.2 CT12.2 CT13.2 CT15.2 CT16.2 CT17.2 CT18.2 CT19.2 CT20.2 CT21.1 CT22.2 CT23.2 CT24.2 CT25.2 CT26.2 CT27.2 CT28.1 CT29.1 CT30.1 CT31.1 CT32.2 CT33.2 CT34.2 CT35.2 CT36.2 CT37.2 CT38.1 CT39.1 CT40.1 CT41.1 J1.2 J2.6 J7.2 L5.1 L6.1 L7.2 L8.2 L11.1 L12.1 LED2.2(CATHODE) Q2.EMITTER Q6.EMITTER R1.1 R3.2 R4.2 R8.1 R11.2 R14.2 R15.2 R17.2 R18.2 R34.2 R35.2 R40.2 R52.1 R53.2 R54.2 R62.1 R69.2 R130.2 R132.1 R143.2 R144.1 R149.1 R159.2 R160.1 R172.1 RN1.2(R1) RN1.4(R2) RN1.6(R3) RN1.8(R4) RN2.2(R1) RN2.4(R2) RN2.6(R3) RN2.8(R4) RP1.2(R1) SW5.2 U1.2(GND) U1.9(GND) U2.2(GND) U3.2(GND) U4.2(GND) U5.11(VSS) U5.13(MVSS) U5.15(MVSS) U5.17(MVSS) U5.19(VSS) U5.81(VSS) U5.103(VSS) U5.145(VSS) U5.147(MVSS) U5.149(MVSS) U5.151(MVSS) U5.153(VSS) U5.165(PLL_VSS) U5.186(VSS) U5.202(VSS) U5.205(USB1_VSS) U5.211(USB0_VSS) U6.15(GND) U7.10(GND) U8.4(GND) U9.2(VSS) U9.13(VSS) U9.23(VSS) U9.25(VSS) U9.36(VSS) U9.48(VSS) U10.12(VSSD) U10.18(MODE) U10.24(VSSSPK) U10.28(VSSA) U10.33(EPAD) U11.5(GND) U12.15(GND) U13.2(GND) U14.33(EPad) U16.33(EPad) U18.1(GND) X2.2(GND) X2.4(GND) X3.2(GND) X3.4(GND) X4.2(GND) X4.4(GND)
ADC0: BT1.2 D3.1(2) J1.1 U5.55(ADC0)
ADC3: R104.1 U5.63(ADC3)
ADC4: R105.1 U5.57(ADC4)
ADC5: R106.1 U5.61(ADC5)
ADC6: R107.1 U5.56(ADC6)
ADC7: R108.1 U5.60(ADC7)
PA0: R72.1 SW4.1(A1) U5.54(PA.0/LD0)
PA1: R73.1 SW4.2(A2) U5.53(PA.1/LD1)
PA2: R74.1 S2.1(\) U5.52(PA.2/LD2)
PA3: R75.1 S3.1(\) U5.51(PA.3/LD3)
PA4: R76.1 S4.1(\) U5.50(PA.4/LD4/KPI_Row0)
PA5: R77.1 S5.1(\) U5.49(PA.5/LD5/KPI_Row1)
PA6: R78.1 S6.1(\) U5.48(PA.6/LD6/KPI_Row2)
PA7: R79.1 S7.1(\) U5.47(PA.7/LD7/KPI_Row3)
PA8: R80.1 S8.1(\) U5.46(PA.8/LD8/KPI_Col0)
PA9: R81.1 S9.1(\) U5.45(PA.9/LD9/KPI_Col1)
PA10: R82.1 U5.43(PA.10/LD10/KPI_Col2)
PA11: R83.1 U5.42(PA.11/LD11/KPI_Col3)
PA12: R89.1 U5.41(PA.12/LD12/KPI_Col4/PWM0)
PA13: R84.1 U5.40(PA.13/LD13/KPI_Col5/PWM1)
PA14: R85.1 U5.39(PA.14/LD14/KPI_Col6/PWM2)
PA15: R86.1 U5.38(PA.15/LD15/KPI_Col7/PWM3)
PB0: CON7.7 U5.105(PB.0/NCS1/IIC1SCL/UR5Tx/SPI0CS1/TM1TGL)
PB1: CON7.9 U5.106(PB.1/NRDY1/IIC1SDA/UR5Rx/SPI1CS1/TM1CAP)
PB2: R100.1 U5.107(PB.2/UR6Tx/PWM0/TM0TGL)
PB4: K1.1 K3.2 K5.1 U5.109(PB.4/UR6RTS)
PB5: K2.1 K4.1 K6.1 U5.110(PB.5/UR6CTS)
PB6: R44.1 U5.111(PB.6/SPI0CS0) U7.7(CS) U8.1(/CS)
PB7: U5.112(PB.7/SPI0Clk) U7.16(CLK) U8.6(CLK)
PB8: U5.113(PB.8/SPI0Do(D0)) U7.15(Di/D0) U8.5(Di/D0)
PB9: U5.114(PB.9/SPI0Di(D1)) U7.8(Do/D1) U8.2(Do/D1)
PB10: R41.1 U5.115(PB.10/UR10Tx/SPI0D2/CAN0Rx) U7.9(Wp/D2) U8.3(Wp/D2)
PB11: R42.1 U5.116(PB.11/UR10Rx/SPI0D3/CAN0Tx) U7.1(Hld/D3) U8.7(Hld/D3)
PB12: CON7.21 U5.117(PB.12/UR10Tx/SPI1CS0)
PB13: CON7.23 U5.118(PB.13/UR10Rx/SPI1Clk)
PB14: CON7.25 U5.119(PB.14/UR10RTS/SPI1Do(D0))
PB15: CON7.27 U5.120(PB.15/UR10CTS/SPI1Di(D1))
PC0: U5.123(PC.0/ND0/eMMC_D0) U9.29(I/O0)
PC1: U5.124(PC.1/ND1/eMMC_D1) U9.30(I/O1)
PC2: U5.125(PC.2/ND2/eMMC_D2) U9.31(I/O2)
PC3: U5.126(PC.3/ND3/eMMC_D3) U9.32(I/O3)
PC4: U5.127(PC.4/ND4/eMMC_CMD) U9.41(I/O4)
PC5: U5.128(PC.5/ND5/eMMC_CLK) U9.42(I/O5)
PC6: U5.129(PC.6/ND6/UR10Tx/TM0TGL) U9.43(I/O6)
PC7: U5.130(PC.7/ND7/UR10Tx/TM0CAP) U9.44(I/O7)
PC8: U5.131(PC.8/NCS0/UR10RTS/TM1TGL) U9.9(~{CE1})
PC9: U5.132(PC.9/NALE/UR10CTS/TM1CAP) U9.17(ALE)
PC10: U5.133(PC.10/NCLE/UR4Tx/TM2TGL) U9.16(CLE)
PC11: U5.134(PC.11/NWE/UR4Rx/TM2CAP) U9.18(~{WE})
PC12: U5.135(PC.12/NRE/UR4RTS/TM3TGL) U9.8(~{RE})
PC13: R46.1 U5.136(PC.13/NRDY0/UR4CTS/TM3CAP) U9.7(R/~{B1})
PC14: R45.1 U5.137(PC.14/NWP/PWM0) U9.19(N.C.)
PD0: CON3.3(CMD) RR2.5(R3) U5.155(PD.0/SD0CMD)
PD1: R47.2 U5.156(PD.1/SD0CLK)
PD2: CON3.7(DAT0) RR1.1(R1) U5.157(PD.2/SD0D0)
PD3: CON3.8(DAT1) RR1.3(R2) U5.158(PD.3/SD0D1)
PD4: CON3.1(DAT2) RR2.1(R1) U5.159(PD.4/SD0D2)
PD5: CON3.2(DAT3) RR2.3(R2) U5.160(PD.5/SD0D3)
PD6: CON3.9(CD) RR1.5(R3) U5.161(PD.6/SD0CD)
PD7: R101.1 U5.162(PD.7/SD0PWR)
PD8: R87.1 U5.37(PD.8/LD16/EBI_nCS0)
PD9: R90.1 U5.36(PD.9/LD17/EBI_nCS1)
PD10: R88.1 U5.35(PD.10/LD18/EBI_nCS2)
PD11: R91.1 U5.34(PD.11/LD19/UR9Tx/EBI_nCS3)
PD12: R92.1 U5.33(PD.12/LD20/UR9Rx/PWM0/EBI_nCS4)
PD13: R93.1 U5.32(PD.13/LD21/PWM1/EBI_nWE)
PD14: R94.1 U5.31(PD.14/LD22/UR9Tx/PWM2/EBI_nOE)
PD15: R95.1 U5.30(PD.15/LD23/UR9Rx/PWM3/EBI_nWait)
PE0: J3.2 R39.1 U5.182(PE.0/UR0Tx)
PE1: J3.1 R38.1 U5.181(PE.1/UR0Rx)
PE2: U5.180(PE.2/RMII1_MDC/SD1CMD/UR1Tx) U16.22(MDC)
PE3: R150.2 U5.179(PE.3/RMII1_MDIO/SD1CLK/UR1Rx) U16.23(MDIO)
PE4: U5.178(PE.4/RMII1_TxD0/SD1D0/UR1RTS) U16.9(TxD0)
PE5: U5.177(PE.5/RMII1_TxD1/SD1D1/UR1CTS) U16.8(TxD1)
PE6: U5.176(PE.6/RMII1_TxEn/SD1D2/UR1DTR) U16.5(TxEn)
PE7: R152.1 U5.175(PE.7/RMII1_RefClk/SD1D3/UR1DSR) U16.14(RxClk/50M_Clko)
PE8: U5.174(PE.8/RMII1_RxD0/SD1CD/UR1Ri) U16.18(RxD0)
PE9: U5.173(PE.9/RMII1_RxD1/SD1PWR/UR1CD) U16.17(RxD1)
PE10: R160.2 U5.172(PE.10/RMII1_CRSDV/UR8Tx) U16.19(RxDV/CRS_DV)
PE11: R151.2 U5.171(PE.11/RMII1_RxErr/UR8Rx) U16.21(RxEr/Int32)
PE12: CON7.3 U5.170(PE.12/UR8RTS/UR3Tx)
PE13: CON7.5 U5.169(PE.13/UR8CTS/UR3Rx)
PE14: K5.3 K6.3 U5.201(PE.14/USB0PWREn)
PE15: K3.4 K4.3 U5.200(PE.15/USB1PWREn)
PF0: U5.196(PF.0/RMII0_MDC) U14.22(MDC)
PF1: R133.2 U5.195(PF.1/RMII0_MDio) U14.23(MDIO)
PF2: U5.194(PF.2/RMII0_TxD0) U14.9(TxD0)
PF3: U5.193(PF.3/RMII0_TxD1) U14.8(TxD1)
PF4: U5.192(PF.4/RMII0_TxEn) U14.5(TxEn)
PF5: R135.1 U5.191(PF.5/RMII0_RefClk) U14.14(RxClk/50M_Clko)
PF6: U5.190(PF.6/RMII0_RxD0) U14.18(RxD0)
PF7: U5.189(PF.7/RMII0_RxD1) U14.17(RxD1)
PF8: R144.2 U5.188(PF.8/RMII0_CRSDV) U14.19(RxDV/CRS_DV)
PF9: R134.2 U5.187(PF.9/RMII0_RxErr) U14.21(RxEr/Int32)
PF10: K1.3 K2.3 U5.199(PF.10/USBPWREn/WDT_nRst)
PF11: J6.1 U5.25(PF.11/UR2Tx/TM2TGL/Int0) U12.11(T1in)
PF12: J6.2 U5.24(PF.12/UR2Rx/TM2CAP/Int1) U12.12(R1o)
PF13: J6.3 U5.23(PF.13/UR2RTS/TM3TGL/Int2) U12.10(T2in)
PF14: J6.4 U5.22(PF.14/UR2CTS/TM3CAP/Int3) U12.9(R2o)
PG0: R55.2 R57.2 R110.1 U5.4(PG.0/IIC0SCL)
PG1: R56.2 R59.2 R111.1 U5.3(PG.1/IIC0SDA)
PG2: R128.1 U5.2(PG.2/IIC1SCL)
PG3: R129.1 U5.1(PG.3/IIC1SDA)
PG4: R103.1 U5.121(PG.4/NCS1/UR7Tx/SPI1D2)
PG5: R109.1 U5.122(PG.5/NRDY1/UR7Rx/SPI1D3)
PG6: R96.1 U5.29(PG.6/LClk)
PG7: R97.1 U5.28(PG.7/LHsync)
PG8: R98.1 U5.27(PG.8/LVsync)
PG9: R99.1 U5.26(PG.9/LDEN)
PG10: R58.2 U5.9(PG.10/IIS_MClk/SC0_RST)
PG11: R60.2 U5.8(PG.11/IIS_DO/SC0_CLK/UR6Tx)
PG12: R61.2 U5.7(PG.12/IIS_DI/SC0_DAT/UR6Rx)
PG13: R63.2 U5.6(PG.13/IIS_BCLK/SC0PWR/UR6RTS)
PG14: R67.2 U5.5(PG.14/IIS_LRCK/SC0CD/UR6CTS)
PH0: R165.1 R172.2 U5.198(PH.0/USB0VbusVLD/Int0)
PH1: C29.2 R137.2 U5.197(PH.1/USBOC/Int1) U14.32(nRst) U16.32(nRst)
PH2: LED3.2(CATHODE) U5.168(PH.2/IIC1SCL/UR9Tx/CAN0Rx/PWM2/Int2)
PH3: R102.1 U5.167(PH.3/IIC1SDA/UR9Rx/CAN0Tx/PWM3/Int3)
PH4: CON7.4 U5.71(PH.4/KPI_Row0/UR1Tx/EBI_Add0/Int4)
PH5: CON7.6 U5.72(PH.5/KPI_Row1/UR1Rx/EBI_Add1/Int5)
PH6: CON7.8 U5.73(PH.6/KPI_Row2/SD1Cmd/UR1RTS/EBI_Add2/Int6)
PH7: CON7.10 U5.74(PH.7/KPI_Row3/SD1Clk/UR1CTS/EBI_Add3/Int7)
PH8: CON7.12 U5.75(PH.8/KPI_Col0/SD1D0/UR4Tx/EBI_Add4)
PH9: CON7.14 U5.76(PH.9/KPI_Col1/SD1D1/UR4Rx/EBI_Add5)
PH10: CON7.16 U5.77(PH.10/KPI_Col2/SD1D2/UR4RTS/EBI_Add6)
PH11: CON7.18 U5.78(PH.11/KPI_Col3/SD1D3/UR4CTS/EBI_Add7)
PH12: CON7.22 U5.79(PH.12/KPI_Cl4/SD1CD/UR8Tx/SPI0CS1/EBI_Add8)
PH13: CON7.24 U5.83(PH.13/KPI_Col5/SD1PWR/UR8Rx/SPI1CS1/EBI_Add9)
PH14: CON7.26 U5.84(PH.14/KPI_Col6/UR8RTS/CAN1Rx/EBI_nBE0)
PH15: CON7.28 U5.85(PH.15/KPI_Col7/UR8CTS/CAN1Tx/EBI_nBE1)
PHY_AVDD33: CB46.2 CB49.2 CT34.1 CT35.1 L10.2 U14.31(AVD33) U16.31(AVD33)
PHY_DVDD33: CB45.2 CB51.2 CON12.10(LED+) CON13.10(LED+) CT33.1 CT37.1 L9.2 R133.1 R134.1 R138.2 R139.1 R142.2 R150.1 R151.1 R154.2 R155.1 R158.2 U14.13(IOVDD) U16.13(IOVDD)
PI0: R112.1 U5.86(PI.0/EBI_D0)
PI1: CON7.11 U5.87(PI.1/NCS0/UR7Tx/EBI_D1/Int6)
PI2: CON7.13 U5.88(PI.2/NWP/UR7Rx/EBI_D2/Int7)
PI3: R113.2 U5.89(PI.3/SClko/NALE/IIC1SCL/EBI_D3)
PI4: R114.2 U5.90(PI.4/SPClk/NCLE/IIC1SDA/EBI_D4)
PI5: R117.1 U5.91(PI.5/SHsync/NWE/eMMC_Cmd/EBI_D5/SD1CMD)
PI6: R118.1 U5.92(PI.6/SVsync/NRE/eMMC_Clk/SC1_Rst/EBI_D6/SD1CLK)
PI7: R119.1 U5.93(PI.7/SField/NRDY0/eMMC_D3/SC1_Clk/EBI_D7/SD1D0)
PI8: R120.1 U5.94(PI.8/SD0/ND0/eMMC_D0/SC1_DAT/EBI_D8/SD1D1)
PI9: R121.1 U5.95(PI.9/SD1/ND1/eMMC_D1/SC1_PWR/EBI_D9/SD1D2)
PI10: R122.1 U5.96(PI.10/SD2/ND2/eMMC_D2/SC1_CD/EBI_D10/SD1D3)
PI11: R123.1 U5.97(PI.11/SD3/ND3/SC0_Rst/EBI_D11)
PI12: R124.1 U5.98(PI.12/SD4/ND4/UR8Tx/SC0_Clk/EBI_D12/SD1CD)
PI13: R125.1 U5.99(PI.13/SD5/ND5/UR8Rx/SC0_DAT/EBI_D13/SD1PWR)
PI14: R126.1 U5.100(PI.14/SD6/ND6/UR8RTS/SC0_PWR/EBI_D14)
PI15: R127.1 U5.101(PI.15/SD7/ND7/UR8CTS/SC0_CD/EBI_D15)
PJ0: J2.5 RP1.1(R1) U5.139(PJ.0/TCK)
PJ1: J2.4 RP1.3(R2) U5.140(PJ.1/TMS)
PJ2: J2.3 RP1.5(R3) U5.141(PJ.2/TDI)
PJ3: J2.7 U5.138(PJ.3/TDO)
PJ4: J2.2 RP1.7(R4) U5.142(PJ.4/nTRST)
RESET: C16.2 Q2.COLLECTOR R19.1 R33.2 R37.2 SW5.3
RTC_VDD33: C4.1 CB23.1 D2.2(1) D3.2(1) U5.66(RTC_VDD)
SCHEMATIC03/12M_XI: C12.1 R22.2 U5.184(MainXi) X2.1(XIN)
SCHEMATIC03/12M_XO: C13.1 R22.1 U5.185(MainXo) X2.3(XOUT)
SCHEMATIC03/ADC1: T1.\ U5.62(ADC1)
SCHEMATIC03/ADC2: T2.\ U5.64(ADC2)
SCHEMATIC03/BEEPER: R21.1 U5.108(PB.3/UR6Rx/PWM1/TM0CAP)
SCHEMATIC03/nRST: L4.2 U5.143(nRESET)
SCHEMATIC03/RTC_XI: C10.1 U5.69(RTCXi) X1.2
SCHEMATIC03/RTC_XO: C11.1 U5.70(RTCXo) X1.1
SCHEMATIC04/UR0_RX: CON2.3 U6.13(R1in)
SCHEMATIC04/UR0_RXD: R38.2 U6.12(R1o)
SCHEMATIC04/UR0_TX: CON2.2 U6.14(T1o)
SCHEMATIC04/UR0_TXD: R39.2 U6.11(T1in)
SCHEMATIC06/485_6_ENB: R69.1 SW8.1(\) U11.2(\\\\RE) U11.3(DE)
SCHEMATIC06/485_6_RX: R65.1 SW7.1(\)
SCHEMATIC06/485_6_TX: R68.1 SW6.1(\)
SCHEMATIC06/485_A6: CON5.1 J5.1 R70.2
SCHEMATIC06/485_B6: CON5.2 J5.2 R64.2
SCHEMATIC06/GPIO2: CON4.7 R51.1 U10.3(LLIN/GPIO2)
SCHEMATIC06/I2C0_SCL: C25.2 R57.1 U10.16(SCLK)
SCHEMATIC06/I2C0_SDA: C24.2 R59.1 U10.17(SDIO)
SCHEMATIC06/I2S_BCLK: SW8.3(\) U10.8(BCLK)
SCHEMATIC06/I2S_DI: SW7.3(\) U10.9(ADCOUT)
SCHEMATIC06/I2S_DO: SW6.3(\) U10.10(DACIN)
SCHEMATIC06/I2S_LRCK: R67.1 U10.7(FS)
SCHEMATIC06/I2S_MCLK: R58.1 U10.11(MCLK)
SCHEMATIC06/LHP: C23.2 U10.30(LHP)
SCHEMATIC06/LSPKOUT: J4.2 U10.25(LSP_O)
SCHEMATIC06/MICN: C22.1 U10.2(LMICN)
SCHEMATIC06/MICP: C20.1 U10.1(LMICP)
SCHEMATIC06/RHP: C21.2 U10.29(RHP)
SCHEMATIC06/RSPKOUT: J4.1 U10.23(RSP_O)
SCHEMATIC06/VREF: C19.2 U10.27(VREF)
SCHEMATIC07/UR2CT: CON6.7 U12.8(R2in)
SCHEMATIC07/UR2RT: CON6.8 U12.7(T2o)
SCHEMATIC07/UR2RX: CON6.3 U12.13(R1in)
SCHEMATIC07/UR2TX: CON6.2 U12.14(T1o)
SCHEMATIC08/B0: CON8.32 R72.2
SCHEMATIC08/B1: CON8.31 R73.2
SCHEMATIC08/B2: CON8.30 R74.2
SCHEMATIC08/B3: CON8.29 R75.2
SCHEMATIC08/B4: CON8.28 R76.2
SCHEMATIC08/B5: CON8.27 R77.2
SCHEMATIC08/B6: CON8.26 R78.2
SCHEMATIC08/B7: CON8.25 R79.2
SCHEMATIC08/G0: CON8.24 R80.2
SCHEMATIC08/G1: CON8.23 R81.2
SCHEMATIC08/G2: CON8.22 R82.2
SCHEMATIC08/G3: CON8.21 R83.2
SCHEMATIC08/G4: CON8.20 R89.2
SCHEMATIC08/G5: CON8.19 R84.2
SCHEMATIC08/G6: CON8.18 R85.2
SCHEMATIC08/G7: CON8.17 R86.2
SCHEMATIC08/I2C0_C: CON8.49 R110.2
SCHEMATIC08/I2C0_D: CON8.50 R111.2
SCHEMATIC08/LCD_BLEN: CON8.4 R102.2
SCHEMATIC08/LCD_CLK: CON8.8 R96.2
SCHEMATIC08/LCD_CS: CON8.3 R101.2
SCHEMATIC08/LCD_D16: CON8.16 R87.2
SCHEMATIC08/LCD_D17: CON8.15 R90.2
SCHEMATIC08/LCD_D18: CON8.14 R88.2
SCHEMATIC08/LCD_D19: CON8.13 R91.2
SCHEMATIC08/LCD_D20: CON8.12 R92.2
SCHEMATIC08/LCD_D21: CON8.11 R93.2
SCHEMATIC08/LCD_D22: CON8.10 R94.2
SCHEMATIC08/LCD_D23: CON8.9 R95.2
SCHEMATIC08/LCD_DEN: CON8.5 R99.2
SCHEMATIC08/LCD_HSYNC: CON8.7 R97.2
SCHEMATIC08/LCD_PWM: CON8.37 R100.2
SCHEMATIC08/LCD_RST: CON8.38 R103.2
SCHEMATIC08/LCD_VSYNC: CON8.6 R98.2
SCHEMATIC08/TOUCH_INT: CON8.51 R109.2
SCHEMATIC08/Vsen: CON8.42 R104.2
SCHEMATIC08/XM: CON8.43 R107.2
SCHEMATIC08/XP: CON8.41 R108.2
SCHEMATIC08/YM: CON8.44 R105.2
SCHEMATIC08/YP: CON8.46 R106.2
SCHEMATIC09/CAN0_H: CON11.1 R131.1 U13.7(CANH)
SCHEMATIC09/CAN0_L: CON11.2 R131.2 U13.6(CANL)
SCHEMATIC09/CAN0_RS: R130.1 U13.8(Rs)
SCHEMATIC09/CAN0_RX: SW9.1(\) U13.4(R)
SCHEMATIC09/CAN0_TX: SW10.1(\) U13.1(D)
SCHEMATIC09/I2C1_SCL: CON9.21 CON10.21 R115.1 R128.2
SCHEMATIC09/I2C1_SDA: CON9.22 CON10.22 R116.1 R129.2
SCHEMATIC09/S_Clk: CON9.8 CON10.8 SW9.3(\)
SCHEMATIC09/S_D0: CON9.9 CON10.9 R120.2
SCHEMATIC09/S_D1: CON9.10 CON10.10 R121.2
SCHEMATIC09/S_D2: CON9.11 CON10.11 R122.2
SCHEMATIC09/S_D3: CON9.12 CON10.12 R123.2
SCHEMATIC09/S_D4: CON9.13 CON10.13 R124.2
SCHEMATIC09/S_D5: CON9.14 CON10.14 R125.2
SCHEMATIC09/S_D6: CON9.15 CON10.15 R126.2
SCHEMATIC09/S_D7: CON9.16 CON10.16 R127.2
SCHEMATIC09/S_Hsync: CON9.18 CON10.18 R117.2
SCHEMATIC09/S_nRst: CON9.20 CON10.20 R119.2
SCHEMATIC09/S_PClk: CON9.7 CON10.7 SW10.3(\)
SCHEMATIC09/S_PwDn: CON9.19 CON10.19 R112.2
SCHEMATIC09/S_Vsync: CON9.17 CON10.17 R118.2
SCHEMATIC10/F_COL: R138.1 U14.4(Col/RMII)
SCHEMATIC10/F_CRS: R142.1 U14.20(CRS/LEDMod)
SCHEMATIC10/F_ETH_XI: C28.1 R136.2 U14.2(Xi) X3.1(XIN)
SCHEMATIC10/F_ETH_XO: C30.1 R136.1 U14.3(Xo) X3.3(XOUT)
SCHEMATIC10/F_MDI_RN: U14.26(MDiRn) U15.8(RD-)
SCHEMATIC10/F_MDI_RP: U14.27(MDiRp) U15.6(RD+)
SCHEMATIC10/F_MDI_TN: U14.29(MDiTn) U15.3(TD-)
SCHEMATIC10/F_MDI_TP: U14.30(MDiTp) U15.1(TD+)
SCHEMATIC10/F_PHY_AD0: R139.2 R141.1 U14.11(LED0/PhyAD0)
SCHEMATIC10/F_PHY_AD3: R140.1 R143.1 U14.12(LED3/PhyAD3)
SCHEMATIC10/F_REG_OUT: CB44.2 CT32.1 U14.28(RegOut)
SCHEMATIC10/F_RX+: CON12.3(RX+) U15.11(RX+)
SCHEMATIC10/F_RX-: CON12.6(RX-) U15.9(RX-)
SCHEMATIC10/F_RX_CLK: C27.1 R135.2 U14.10(TxClk/50MClki)
SCHEMATIC10/F_TX+: CON12.1(TX+) U15.16(TX+)
SCHEMATIC10/F_TX-: CON12.2(TX-) U15.14(TX-)
SCHEMATIC11/E_COL: R154.1 U16.4(Col/RMII)
SCHEMATIC11/E_CRS: R158.1 U16.20(CRS/LEDMod)
SCHEMATIC11/E_ETH_XI: C36.1 R153.2 U16.2(Xi) X4.1(XIN)
SCHEMATIC11/E_ETH_XO: C37.1 R153.1 U16.3(Xo) X4.3(XOUT)
SCHEMATIC11/E_MDI_RN: U16.26(MDiRn) U17.8(RD-)
SCHEMATIC11/E_MDI_RP: U16.27(MDiRp) U17.6(RD+)
SCHEMATIC11/E_MDI_TN: U16.29(MDiTn) U17.3(TD-)
SCHEMATIC11/E_MDI_TP: U16.30(MDiTp) U17.1(TD+)
SCHEMATIC11/E_PHY_AD0: R155.2 R157.1 U16.11(LED0/PhyAD0)
SCHEMATIC11/E_PHY_AD3: R156.1 R159.1 U16.12(LED3/PhyAD3)
SCHEMATIC11/E_REG_OUT: CB50.2 CT36.1 U16.28(RegOut)
SCHEMATIC11/E_RX+: CON13.3(RX+) U17.11(RX+)
SCHEMATIC11/E_RX-: CON13.6(RX-) U17.9(RX-)
SCHEMATIC11/E_RX_CLK: C35.1 R152.2 U16.10(TxClk/50MClki)
SCHEMATIC11/E_TX+: CON13.1(TX+) U17.16(TX+)
SCHEMATIC11/E_TX-: CON13.2(TX-) U17.14(TX-)
SP_VDD33: CB35.1 CT27.1 R49.1 U10.26(VDDSPK)
USB0_DM: R167.2 U5.212(USB0_DM)
USB0_DP: R170.2 U5.213(USB0_DP)
USB0_ID: CON14.4(ID) J7.1 R181.1 R182.2 U5.216(USB0_ID)
USB1_DM: R174.2 U5.206(USB1_DM)
USB1_DP: R175.2 U5.207(USB1_DP)
SCHEMATIC02/N16824100: C7.1 CT11.1 L3.2 R13.2 R179.1
SCHEMATIC02/N16824173: C2.2 CT5.1 L1.2 R7.2 R177.1
SCHEMATIC02/N16824179: C2.1 R7.1 R8.2 U2.5(FB)
SCHEMATIC02/N16824181: C5.1 CT8.1 L2.2 R10.2 R178.1
SCHEMATIC02/N16824208: C6.1 R9.1 U3.1(EN)
SCHEMATIC02/N16824212: C7.2 R13.1 R14.1 U4.5(FB)
SCHEMATIC02/N16824268: L2.1 U3.3(SW)
SCHEMATIC02/N16824274: L3.1 U4.3(SW)
SCHEMATIC02/N16824335: C5.2 R10.1 R11.1 U3.5(FB)
SCHEMATIC02/N16824467: LED1.2(CATHODE) U1.4(#Fault)
SCHEMATIC02/N16824469: R4.1 U1.7(Ilimit)
SCHEMATIC02/N16824533: R3.1 U1.5(#En) U1.6(Bat)
SCHEMATIC02/N16824640: CON1.1 SW_POWER1.3(NO1)
SCHEMATIC02/N16825262: L1.1 U2.3(SW)
SCHEMATIC02/N16826632: C8.1 R12.1 U4.1(EN)
SCHEMATIC02/N16830709: LED1.1(ANODE) R6.1
SCHEMATIC02/N16866619: LED2.1(ANODE) R2.1
SCHEMATIC02/N16870045: C3.1 R5.1 U2.1(EN)
SCHEMATIC03/N16926186: R15.1 U5.209(USB1_Rext)
SCHEMATIC03/N16926334: C14.2 U5.65(Vref)
SCHEMATIC03/N16930212: R17.1 U5.215(USB0_Rext)
SCHEMATIC03/N16938327: Q1.2 R20.2
SCHEMATIC03/N16938341: Q1.1 R21.2
SCHEMATIC03/N16938343: BZ1.1(+) Q1.3
SCHEMATIC03/N16939334: C9.2 L4.1 R19.2
SCHEMATIC04/N16818927: R28.1 RN2.3(R2) S5.2(\)
SCHEMATIC04/N16820996: CB27.1 U6.5(C2-)
SCHEMATIC04/N16820998: CB27.2 U6.4(C2+)
SCHEMATIC04/N16821000: CB25.2 U6.1(C1+)
SCHEMATIC04/N16821002: CB25.1 U6.3(C1-)
SCHEMATIC04/N16821008: CB28.2 U6.6(V-)
SCHEMATIC04/N16821016: CB26.2 U6.2(V+)
SCHEMATIC04/N16821295: C17.2 CON2.10 CON2.11
SCHEMATIC04/N16821300: CON2.5 L5.2
SCHEMATIC04/N16831437: C15.1 Q2.BASE R40.1
SCHEMATIC04/N16834539: J2.8 R33.1
SCHEMATIC04/N16875062: R23.1 RN1.1(R1) SW4.4(B1)
SCHEMATIC04/N16875067: R24.1 RN1.3(R2) SW4.3(B2)
SCHEMATIC04/N16875072: R25.1 RN1.5(R3) S2.2(\)
SCHEMATIC04/N16875077: R26.1 RN1.7(R4) S3.2(\)
SCHEMATIC04/N16875082: R27.1 RN2.1(R1) S4.2(\)
SCHEMATIC04/N16875093: R29.1 RN2.5(R3) S6.2(\)
SCHEMATIC04/N16875098: R30.1 RN2.7(R4) S7.2(\)
SCHEMATIC04/N16875103: R31.1 R34.1 S8.2(\)
SCHEMATIC04/N16875108: R32.1 R35.1 S9.2(\)
SCHEMATIC04/N16889736: LED3.1(ANODE) R36.1
SCHEMATIC05/N16177340: R43.1 U7.3(/Rst)
SCHEMATIC05/N16424571: T4.\ U9.6(R/B2)
SCHEMATIC05/N16424573: T5.\ U9.10(/CE2)
SCHEMATIC05/N16424577: T3.\ U9.38(PRE)
SCHEMATIC05/N16426180: T6.\ U9.39(PSL)
SCHEMATIC05/N16507398: CON3.10(GND) CON3.11(GND) CON3.12(GND) CON3.13(GND) L6.2
SCHEMATIC05/N16507502: C18.1 CON3.5(CLK) R47.1
SCHEMATIC06/N16836167: C22.2 M1.N(2) R52.2
SCHEMATIC06/N16836169: C20.2 M1.P(1) R50.1
SCHEMATIC06/N16836231: R48.1 U10.32(MICBIAS)
SCHEMATIC06/N16836533: CB36.2 CT28.2 R48.2 R50.2
SCHEMATIC06/N16852121: C23.1 CON4.4 R54.1
SCHEMATIC06/N16852139: C21.1 CON4.3 R53.1
SCHEMATIC06/N16863870: R62.2 R64.1 R66.2 U11.7(B)
SCHEMATIC06/N16863919: R65.2 U11.1(RO)
SCHEMATIC06/N16863946: R66.1 R70.1 R71.1 U11.6(A)
SCHEMATIC06/N16863961: R68.2 U11.4(DI)
SCHEMATIC06/N16872256: CON4.1 L7.1
SCHEMATIC06/N16873161: R60.1 SW6.2(\)
SCHEMATIC06/N16873479: R61.1 SW7.2(\)
SCHEMATIC06/N16873487: R63.1 SW8.2(\)
SCHEMATIC07/N16492316: CB41.1 U12.5(C2-)
SCHEMATIC07/N16492336: CB41.2 U12.4(C2+)
SCHEMATIC07/N16492340: CB38.2 U12.1(C1+)
SCHEMATIC07/N16492344: CB38.1 U12.3(C1-)
SCHEMATIC07/N16492356: CB39.2 U12.2(V+)
SCHEMATIC07/N16492366: CB42.2 U12.6(V-)
SCHEMATIC07/N16492602: C26.2 CON6.10 CON6.11
SCHEMATIC07/N16492668: CON6.5 L8.1
SCHEMATIC09/N16503874: R113.1 SW9.2(\)
SCHEMATIC09/N16504046: R114.1 SW10.2(\)
SCHEMATIC10/N43037: C32.1 CB48.1 U15.2(CT)
SCHEMATIC10/N43057: C33.1 C34.1 CON12.13(Shield) CON12.14(Shield)
SCHEMATIC10/N43211: R148.2 U15.15(CT)
SCHEMATIC10/N43221: CON12.7(NC) CON12.8(NC) R145.2
SCHEMATIC10/N43237: CON12.4(NC) CON12.5(NC) R146.2
SCHEMATIC10/N43369: R147.2 U15.10(CT)
SCHEMATIC10/N44057: C31.1 CB47.1 U15.7(CT)
SCHEMATIC10/N44589: R132.2 U14.25(Iset)
SCHEMATIC10/N44889: CON12.9(LED-) R141.2
SCHEMATIC10/N45241: C33.2 R145.1 R146.1 R147.1 R148.1
SCHEMATIC10/N16824163: CON12.12(LED+) R140.2
SCHEMATIC11/N43037: C39.1 CB53.1 U17.2(CT)
SCHEMATIC11/N43057: C40.1 C41.1 CON13.13(Shield) CON13.14(Shield)
SCHEMATIC11/N43211: R164.2 U17.15(CT)
SCHEMATIC11/N43221: CON13.7(NC) CON13.8(NC) R161.2
SCHEMATIC11/N43237: CON13.4(NC) CON13.5(NC) R162.2
SCHEMATIC11/N43369: R163.2 U17.10(CT)
SCHEMATIC11/N44057: C38.1 CB52.1 U17.7(CT)
SCHEMATIC11/N44589: R149.2 U16.25(Iset)
SCHEMATIC11/N44889: CON13.9(LED-) R157.2
SCHEMATIC11/N45241: C40.2 R161.1 R162.1 R163.1 R164.1
SCHEMATIC11/N16824163: CON13.12(LED+) R156.2
SCHEMATIC12/N16262807: C43.1 CON14.6(\) CON14.7(\) CON14.8(\) CON14.9(\)
SCHEMATIC12/N16262897: CON14.2(D-) R167.1
SCHEMATIC12/N16262905: CON14.3(D+) R170.1
SCHEMATIC12/N16262999: C42.2 CON14.1(V+) F1.1
SCHEMATIC12/N16263155: CON14.5(GND) L11.2
SCHEMATIC12/N16263828: CON15.2(D-) R174.1
SCHEMATIC12/N16263840: CON15.3(D+) R175.1
SCHEMATIC12/N16263954: CON15.1(VBUS) CT38.2 F2.1
SCHEMATIC12/N16263998: C44.1 CON15.5(Shield) CON15.6(Shield)
SCHEMATIC12/N16267023: CB54.2 CT41.2 F1.2 Q5.2(S) U18.6(Vout) U18.7(Vout) U18.8(Vout)
SCHEMATIC12/N16463622: CON15.4(GND) L12.2
SCHEMATIC12/N16563281: Q6.COLLECTOR R169.2 R180.1 U18.4(En)
SCHEMATIC12/N16563377: Q5.3(D) R165.2
SCHEMATIC12/N16563595: Q6.BASE R182.1
SCHEMATIC12/N16564866: Q5.1(G) R169.1

Not connected (* = marked no-connect by the designer): CON2 1* 4* 6* 7* 8* 9*; CON4 5 6; CON6 1* 4* 6* 9*; CON7 15 17; CON8 33 34 35 36 45 52 53 54 55 56 57 58 61 62; CON9 5 6; CON10 5 6; K1 2 4*; K2 2 4*; K3 1* 3; K4 2 4*; K5 2 4*; K6 2 4*; RR1 7(R4)*; RR2 7(R4)*; SW5 1* 4*; SW_POWER1 1(NC1)* 4(NC2)* 5(COMMON2)* 6(NO2)*; U1 3(N.C.)*; U5 67(SysPWREn)* 68(SysnWkUp)*; U6 7(T2o)* 8(R2in)* 9(R2o)* 10(T2in)*; U7 4(NC)* 5(NC)* 6(NC)* 11(NC)* 12(NC)* 13(NC)* 14(NC)*; U10 4(RMICP) 5(RMICN) 6(RLIN/GPIO3) 15(CSB/GPIO1) 19(LAUXIN) 20(RAUXIN) 21(AUXOUT1) 22(AUXOUT2); U13 5(Vref)*; U14 1(TxEr/FxSD)* 6(TxD3)* 7(TxD2)* 15(RxD3)* 16(RxD2)* 24(TestOn); U15 4(NC)* 5(NC)* 12(NC)* 13(NC)*; U16 1(TxEr/FxSD)* 6(TxD3)* 7(TxD2)* 15(RxD3)* 16(RxD2)* 24(TestOn); U17 4(NC)* 5(NC)* 12(NC)* 13(NC)*; U18 5(\\~{O}C)

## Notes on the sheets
sheet 2
- Ethernet1_PE
sheet 3
- RS-232_2
- TX2
- RX2
- RT2
- CT2
- VDD33
- VDD33
- TX1
- TX3
- RX1
- RX3
- RT1
- TX5
- CT1
- RX5
- RX4
- TX4
- RX7
- TX7
- RT4
- CT4
- VSS
- VSS
- TX8
- TX10
- RT8
- RX8
- RT10
- RX10
- CT8
- CT10
- VDD5
- VDD5
sheet 4
- 1-2: CAN_0
- 2-3: CMOS Sensor
- CMOS Sensor
- CMOS Sensor
- H
- L
- CAN_0
sheet 5
- Earphone
- 7
- 6
- 4
- R
- 1
- 2
- 3
- 5
- Speaker
- L
- 1-2: RS-485_6
- 2-3: I2S
- B6
- RS-485_6
- A6
sheet 6
- 24Bit LCD Interface
- RGB 888
sheet 7
- USB0 Device/HOST
- Short:USB0 HOST
- USB1 HOST
sheet 8
- Ethernet0_PF
sheet 9
- S0(A1)
- S1(A0)
- Boot
- Power On Setting
- ON
- ON
- USB
- OFF
- ON
- OFF
- ON
- NAND
- eMMC
- OFF
- OFF
- SPI
- S2(A2)
- Clock
- ICE I/F
- O
- 12MHz
- S0
- X
- UPLL
- S3(A3)
- Watch Dog
- VDD33
- S1
- O
- OFF
- TRST
- X
- ON
- TDI
- TMS
- S4(A4)
- PJ[4:0]
- TCK
- O
- X
- GPIO
- JTAG
- TDO
- VSS
- RST
- S5(A5)
- UART0 Message
- O
- ON
- X
- OFF
- S7(A7)
- O
- S6(A6)
- O
- 2KB
- NAND Page Size
- O
- X
- 4KB
- X
- O
- 8KB
- PH2
- X
- X
- None
- G
- S9(A9)
- O
- S8(A8)
- O
- NAND ECC
- T12
- O
- X
- T15
- X
- O
- T24
- X
- X
- None
- RX0
- TX0
- Reset
- RS-232_0
sheet 10
- 5V IN
- P_Fault
- P_Good
- G
- R
- VDD33
- VDD12
- RTC 3.3V
- +
- RTC Battery
- -
- VDD18
sheet 11
- PIN
- FUNCTION
- PIN
- FUNCTION
- PIN
- FUNCTION
- PIN
- FUNCTION
- PIN
- FUNCTION
- PIN
- FUNCTION
- PIN
- FUNCTION
- PIN
- FUNCTION
- PIN
- FUNCTION
- PIN
- FUNCTION
- PA0
- LCD_DATA0
- PB0
- RS232_5_TXD
- PC0
- NAND_D0
- PD0
- SD0_CMD
- PE0
- RS232_0_TXD
- PF0
- RMII0_MDC
- PG0
- I2S_I2C0_SCL
- PH0
- USB0_VBUSVLD
- PI0
- VCAP_PwDN
- PJ0
- JTAG_TCK
- PwrOnSet0
- LCD_I2C0_SCL
- LCD_DATA1
- PB1
- RS232_5_RXD
- PC1
- NAND_D1
- PD1
- SD0_CLK
- PE1
- RS232_0_RXD
- PF1
- RMII0_MDIO
- I2S_I2C0_SDA
- PH1
- RMII_RST
- PI1
- RS232_7_TXD
- PJ1
- JTAG_TMS
- PA1
- PG1
- PwrOnSet1
- LCD_I2C0_SDA
- LCD_DATA2
- PB2
- LCD_PWM
- PC2
- NAND_D2
- PD2
- SD0_DATA0
- PE2
- RMII1_MDC
- PF2
- RMII0_TXD0
- PH2
- Indicator_LED
- PI2
- RS232_7_RXD
- PJ2
- JTAG_TDI
- PA2
- PG2
- VCAP_I2C1_SCL
- CAN0_RXD
- PwrOnSet2
- PB3
- Buzzer
- PC3
- NAND_D3
- PD3
- SD0_DATA1
- PE3
- RMII1_MDIO
- PF3
- RMII0_TXD1
- PH3
- LCD_BLEN
- PI3
- PJ3
- JTAG_TDO
- VCAP_CLKO
- LCD_DATA3
- PG3
- VCAP_I2C1_SDA
- PA3
- PwrOnSet3
- PB4
- KEY_Col0
- PC4
- NAND_D4
- PD4
- SD0_DATA2
- PE4
- RMII1_TXD0
- PF4
- RMII0_TXEN
- PH4
- RS232_1_TXD
- PI4
- CAN0_TXD
- PJ4
- JTAG_NTRST
- PG4
- LCD_RST
- VCAP_PCLK
- LCD_DATA4
- PB5
- KEY_Col1
- PC5
- NAND_D5
- PD5
- SD0_DATA3
- PE5
- RMII1_TXD1
- PF5
- RMII0_REFCLK
- PH5
- RS232_1_RXD
- PA4
- PwrOnSet4
- PG5
- TOUCH_INT
- PI5
- VCAP_HSYNC
- PIN
- FUNCTION
- PB6
- SPI0_SS0
- PC6
- NAND_D6
- PD6
- SD0_CD
- PE6
- RMII1_TXEN
- PF6
- RMII0_RXD0
- PH6
- RS232_1_RTS
- PA5
- LCD_DATA5
- PG6
- LCD_CLK
- PI6
- VCAP_VSYNC
- ADC0
- BAT_LVD
- PwrOnSet5
- PB7
- SPI0_CLK
- PC7
- NAND_D7
- PD7
- LCD_CS
- PE7
- RMII1_REFCLK
- PF7
- RMII0_RXD1
- PH7
- RS232_1_CTS
- VCAP_nRST
- LCD_DATA6
- PG7
- LCD_HSYNC
- PI7
- ADC1
- PA6
- PB8
- SPI0_DO(DATA0)
- PC8
- NAND_CS0
- PD8
- LCD_DATA16
- PE8
- RMII1_RXD0
- PF8
- RMII0_CRSDV
- PH8
- RS232_4_TXD
- PwrOnSet6
- PG8
- LCD_VSYNC
- ADC2
- LCD_DATA7
- PB9
- SPI0_DI(DATA1)
- PC9
- NAND_ALE
- PD9
- LCD_DATA17
- PE9
- RMII1_RXD1
- PF9
- RMII0_RXERR
- PH9
- RS232_4_RXD
- PI8
- VCAP_DATA0
- PA7
- PwrOnSet7
- PG9
- LCD_DEN
- ADC3
- VSENSE
- PB10
- SPI0_DATA2
- PC10
- NAND_CLE
- PD10
- LCD_DATA18
- PE10
- RMII1_CRSDV
- PF10
- KEY_Row0
- PH10
- RS232_4_RTS
- PI9
- VCAP_DATA1
- LCD_DATA8
- PA8
- PwrOnSet8
- PB11
- SPI0_DATA3
- PC11
- NAND_nWE
- PD11
- LCD_DATA19
- PE11
- RMII1_RXERR
- PF11
- RS232_2_TXD
- PG10
- I2S_MCLK
- PH11
- RS232_4_CTS
- PI10
- VCAP_DATA2
- ADC4
- TP_YM
- I2S_DO
- LCD_DATA9
- PG11
- ADC5
- TP_YP
- PA9
- PB12
- RS232_10_TXD
- PC12
- NAND_nRE
- PD12
- LCD_DATA20
- PE12
- RS232_3_TXD
- PF12
- RS232_2_RXD
- RS485_6_TXD
- PH12
- RS232_8_TXD
- PI11
- VCAP_DATA3
- PwrOnSet9
- PB13
- RS232_10_RXD
- PC13
- NAND_RDY0
- PD13
- LCD_DATA21
- PE13
- RS232_3_RXD
- PF13
- RS232_2_RTS
- PG12
- I2S_DI
- PH13
- RS232_8_RXD
- PI12
- VCAP_DATA4
- ADC6
- TP_XM
- PA10
- LCD_DATA10
- RS485_6_RXD
- ADC7
- TP_XP
- PB14
- RS232_10_RTS
- PC14
- NAND_nWP
- PD14
- LCD_DATA22
- PE14
- KEY_Row2
- PF14
- RS232_2_CTS
- I2S_BCLK
- PH14
- RS232_8_RTS
- PI13
- VCAP_DATA5
- PA11
- LCD_DATA11
- PG13
- RS485_6_ENB
- PA12
- LCD_DATA12
- PB15
- RS232_10_CTS
- PD15
- LCD_DATA23
- PE15
- KEY_Row1
- PH15
- RS232_8_CTS
- PI14
- VCAP_DATA6
- PG14
- I2S_LRCK
- PI15
- VCAP_DATA7
- PA13
- LCD_DATA13
- PA14
- LCD_DATA14
- PA15
- LCD_DATA15
sheet 12
- SD_0
sheet 13
- Buzzer
